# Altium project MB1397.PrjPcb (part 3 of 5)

## Sheet STM32_microcontroller_power.SchDoc: STM32_microcontroller_power
size A4; Date: Not used; ApprovedBy: Not used; CheckedBy: Not used; Author: Not used; CompanyName: STMicroelectronics; DrawnBy: Not used; Engineer: Not used; Organization: Not used; Address1: Not used; Address2: Not used; Address3: Not used; Address4: Not used; DocumentNumber: Not used; Revision: Not used; SheetNumber: 4; SheetTotal: 22
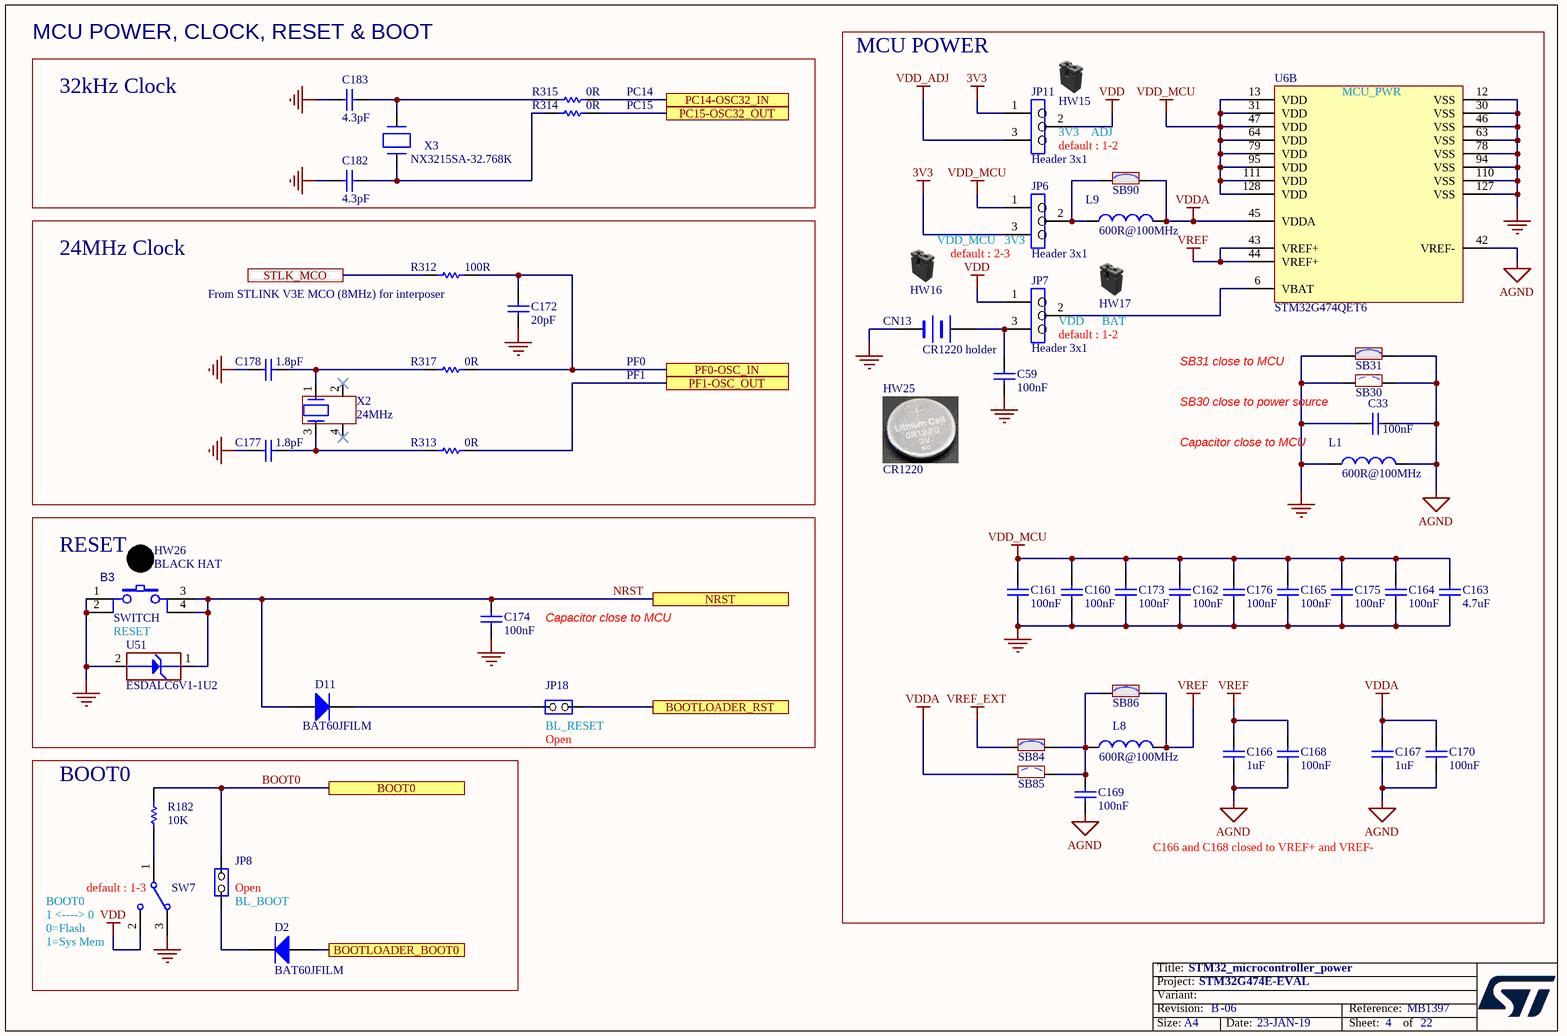
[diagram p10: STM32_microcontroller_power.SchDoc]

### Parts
B3  value SWITCH  [SWI_WEALTHMETAL_TD-0341_4P_BLACK]  (hidden comment: SW-PUSH-CMS)
C33  value 100nF  [C0402]  (hidden comment: Capacitor)
C59  value 100nF  [C0402]  (hidden comment: Capacitor)
C160  value 100nF  [C0402]  (hidden comment: Capacitor)
C161  value 100nF  [C0402]  (hidden comment: Capacitor)
C162  value 100nF  [C0402]  (hidden comment: Capacitor)
C163  value 4.7uF  [C0603]  (hidden comment: Capacitor)
C164  value 100nF  [C0402]  (hidden comment: Capacitor)
C165  value 100nF  [C0402]  (hidden comment: Capacitor)
C166  value 1uF  [C0603]  (hidden comment: Capacitor)
C167  value 1uF  [C0603]  (hidden comment: Capacitor)
C168  value 100nF  [C0402]  (hidden comment: Capacitor)
C169  value 100nF  [C0402]  (hidden comment: Capacitor)
C170  value 100nF  [C0402]  (hidden comment: Capacitor)
C172  value 20pF  [C0402]  (hidden comment: Capacitor)
C173  value 100nF  [C0402]  (hidden comment: Capacitor)
C174  value 100nF  [C0402]  (hidden comment: Capacitor)
C175  value 100nF  [C0402]  (hidden comment: Capacitor)
C176  value 100nF  [C0402]  (hidden comment: Capacitor)
C177  value 1.8pF  [C0402]  (hidden comment: Capacitor)
C178  value 1.8pF  [C0402]  (hidden comment: Capacitor)
C182  value 4.3pF  [C0402]  (hidden comment: Capacitor)
C183  value 4.3pF  [C0402]  (hidden comment: Capacitor)
CN13  value CR1220 holder  [BAT_HARWIN_S8411-45R_SMD_2P]  (hidden comment: BATTERY HOLDER)
D2  BAT60JFILM  [DIO_SOD323]
D11  BAT60JFILM  [DIO_SOD323]
HW15  Shunt Black 2.54mm  (value not drawn)  (mechanical)
HW16  Shunt Black 2.54mm  (value not drawn)  (mechanical)
HW17  Shunt Black 2.54mm  (value not drawn)  (mechanical)
HW25  value CR1220  (hidden comment: BBU_CR1220)  (mechanical)
HW26  value BLACK HAT  (hidden comment: BUTTON_HAT_BLACK)  (mechanical)
JP6  value Header 3x1  [CON_SAMTEC_TSW-103-07-F-S]  (hidden comment: Jumper_Header 3x1)
JP7  value Header 3x1  [CON_SAMTEC_TSW-103-07-F-S]  (hidden comment: Jumper_Header 3x1)
JP8  Jumper_Header 2x1  [CON_SAMTEC_TSW-102-07-G-S]  (value not drawn)
JP11  value Header 3x1  [CON_SAMTEC_TSW-103-07-F-S]  (hidden comment: Jumper_Header 3x1)
JP18  Jumper_Header 2x1  [CON_SAMTEC_TSW-102-07-G-S]  (value not drawn)
L1  value 600R@100MHz  [L0603]  (hidden comment: BEAD)
L8  value 600R@100MHz  [L0603]  (hidden comment: BEAD)
L9  value 600R@100MHz  [L0603]  (hidden comment: BEAD)
R182  value 10K  [R0402]  (hidden comment: Resistor)
R312  value 100R  [R0402]  (hidden comment: Resistor)
R313  value 0R  [R0402]  (hidden comment: Resistor)
R314  value 0R  [R0402]  (hidden comment: Resistor)
R315  value 0R  [R0402]  (hidden comment: Resistor)
R317  value 0R  [R0402]  (hidden comment: Resistor)
SB30  SB_OFF  [SOLDER-BRIDGE_R0603-0R]  (value not drawn)
SB31  SB_ON  [SOLDER-BRIDGE_R0603-0R]  (value not drawn)
SB84  SB_ON  [SOLDER-BRIDGE_R0603-0R]  (value not drawn)
SB85  SB_OFF  [SOLDER-BRIDGE_R0603-0R]  (value not drawn)
SB86  SB_ON  [SOLDER-BRIDGE_R0603-0R]  (value not drawn)
SB90  SB_ON  [SOLDER-BRIDGE_R0603-0R]  (value not drawn)
SW7  SW_MECA_1K2  [SWI_EAO_09-03290-01_EXTENDED_STRAIGHT_BLACK]  (value not drawn)
U6  STM32G474QET6  [ICC_LQFP128_14X14_P040]  (part B of 2)
U51  value ESDALC6V1-1U2  [ESD_ST0201]  (hidden comment: ESD-TRANSIL)
X2  value 24MHz  [CRY_NX2016SA_4P]  (hidden comment: XTAL_4_PINS)
X3  value NX3215SA-32.768K  [CRY_NX3215SA_2P]  (hidden comment: XTAL_2_PINS)

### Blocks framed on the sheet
MCU POWER: C33 C59 C160-C170 C173 C175 C176 CN13 HW15-HW17 HW25 JP6 JP7 JP11 L1 L8 L9 SB30 SB31 SB84-SB86 SB90 U6
24MHz Clock: C172 C177 C178 R312 R313 R317 X2
RESET: B3 C174 D11 HW26 JP18 U51
BOOT0: D2 JP8 R182 SW7

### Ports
BOOT0, BOOTLOADER_BOOT0, BOOTLOADER_RST, NRST, PC14-OSC32_IN, PC15-OSC32_OUT, PF0-OSC_IN, PF1-OSC_OUT, STLK_MCO

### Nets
3V3: JP6.3 JP11.1
AGND: C33.1 C166.1 C167.2 C168.1 C169.1 C170.1 L1.2 SB30.2 SB31.2 U6.42(VREF-)
GND: B3.1 B3.2 C33.2 C59.1 C160.1 C161.1 C162.1 C163.2 C164.1 C165.1 C172.2 C173.1 C174.1 C175.1 C176.1 C177.1 C178.1 C182.1 C183.1 CN13.2(-) L1.1 SB30.1 SB31.1 SW7.3 U6.12(VSS) U6.30(VSS) U6.46(VSS) U6.63(VSS) U6.78(VSS) U6.94(VSS) U6.110(VSS) U6.127(VSS) U51.2(GND)
VDD: JP7.1 JP11.2 SW7.2
VDD_ADJ: JP11.3
VDD_MCU: C160.2 C161.2 C162.2 C163.1 C164.2 C165.2 C173.2 C175.2 C176.2 JP6.1 U6.13(VDD) U6.31(VDD) U6.47(VDD) U6.64(VDD) U6.79(VDD) U6.95(VDD) U6.111(VDD) U6.128(VDD)
VDDA: C167.1 C170.2 L9.2 SB85.1 SB90.2 U6.45(VDDA)
VREF: C166.2 C168.2 L8.2 SB86.2 U6.43(VREF+) U6.44(VREF+)
VREF_EXT: SB84.1
BOOT0: JP8.2(NO) R182.1 ; port BOOT0
NRST: B3.3 B3.4 C174.2 D11.1(A) U51.1(IO1) ; port NRST
PC14: R315.2 ; port PC14-OSC32_IN
PC15: R314.2 ; port PC15-OSC32_OUT
PF0: C172.1 R312.2 R317.2 ; port PF0-OSC_IN
PF1: R313.2 ; port PF1-OSC_OUT
NetC59_2: C59.2 CN13.1(+) JP7.3
NetC169_2: C169.2 L8.1 SB84.2 SB85.2 SB86.1
NetC177_2: C177.2 R313.1 X2.3
NetC178_2: C178.2 R317.1 X2.1
NetC182_2: C182.2 R314.1 X3.1(X1)
NetC183_2: C183.2 R315.1 X3.2(X2)
NetD2_1: D2.1(A) ; port BOOTLOADER_BOOT0
NetD2_2: D2.2(K) JP8.1(COMMON)
NetD11_2: D11.2(K) JP18.1(COMMON)
NetJP6_2: JP6.2 L9.1 SB90.1
NetJP7_2: JP7.2 U6.6(VBAT)
NetJP18_2: JP18.2(NO) ; port BOOTLOADER_RST
NetR182_2: R182.2 SW7.1
NetR312_1: R312.1 ; port STLK_MCO

Not connected (* = marked no-connect by the designer): X2 2* 4*

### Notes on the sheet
- MCU POWER, CLOCK, RESET & BOOT
- 32kHz Clock
- PC14
- PC15
- (near JP11) default : 1-2
- (near JP11) 3V3    ADJ
- VDD_MCU   3V3
- (near R312) From STLINK V3E MCO (8MHz) for interposer
- (near JP6) default : 2-3
- PF0
- PF1
- (near JP7) default : 1-2
- (near JP7) VDD      BAT
- SB31 close to MCU
- (near L1) Capacitor close to MCU
- SB30 close to power source
- (near B3) RESET
- Capacitor close to MCU
- (near JP18) Open
- (near JP18) BL_RESET
- C166 and C168 closed to VREF+ and VREF-
- BOOT0
- (near SW7) 1 <----> 0
- (near SW7) default : 1-3
- (near JP8) Open
- (near JP8) BL_BOOT
- (near SW7) 0=Flash
- (near SW7) 1=Sys Mem

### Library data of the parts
B3 = MCD-00001: Non-Open Push-Button 0.1A 24V BLACK; Manufacturer_Part_Number: TD-0341; Manufacturer: WEALTHMETAL; Part_Type: Misc; Provided_By: SUBCO; Initial_Board_Reference: MB1274; Remark: update MPN removed color, as it is done by HAT, removed Farnell code as it is not good; Path: ws/MCD_ApplicationBoards/Lists/MCDPARTSdatabase; Item Type: Item
C33 C59 C160-C162 C164 C165 C168-C170 C173-C176 = MCD-00006: Capacitor, MLCC, 100nF, 16V, X7R, 10%, 0402, T=0.5mm; Manufacturer_Part_Number: CC0402KRX7R7BB104; Manufacturer: YAGEO; Alternate_Manufacturer_Part_Number: GCM155R71C104KA55D; Alternate_Manufacturer: MURATA; Provided_By: SUBCO; Initial_Board_Reference: MB1274; Path: ws/MCD_ApplicationBoards/Lists/MCDPARTSdatabase; Item Type: Item
C163 = MCD-00009: Capacitor, MLCC, 4.7uF, 16V, X5R, 10%, 0603, T=0.8mm; Manufacturer_Part_Number: CC0603KRX5R7BB475; Manufacturer: YAGEO; Provided_By: SUBCO; Initial_Board_Reference: MB1274; Path: ws/MCD_ApplicationBoards/Lists/MCDPARTSdatabase; Item Type: Item
C166 = MCD-00010: Capacitor, MLCC, 1uF, 16V, X5R, 10%, 0603, T=0,8mm; Manufacturer_Part_Number: CC0603KRX5R7BB105; Manufacturer: YAGEO; Provided_By: SUBCO; ECCN_US: EAR99; ECCN_EU: NEC
C167 = MCD-00010: Capacitor, MLCC, 1uF, 16V, X5R, 10%, 0603, T=0,8mm; Manufacturer_Part_Number: CC0603KRX5R7BB105; Manufacturer: YAGEO; Provided_By: SUBCO; Initial_Board_Reference: MB1274; Path: ws/MCD_ApplicationBoards/Lists/MCDPARTSdatabase; Item Type: Item
C172 = MCD-00016: Capacitor, MLCC, 20pF, 50V, NPO, 5%, 0402, T=0,5mm; Manufacturer_Part_Number: CC0402JRNPO9BN200; Manufacturer: YAGEO; Provided_By: SUBCO; Initial_Board_Reference: MB1274; Path: ws/MCD_ApplicationBoards/Lists/MCDPARTSdatabase; Item Type: Item
C177 C178 = MCD-01598: Capacitor, MLCC, 1.8pF, 50V, NPO, +-0.25pF, 0402, T=0,5mm; Manufacturer_Part_Number: CC0402CRNPO9BN1R8; Manufacturer: YAGEO; Provided_By: SUBCO
C182 C183 = MCD-01706: Capacitor, MLCC, 4.3pF, 50V, NPO, +-0.25pF, 0402, T=0,5mm; Manufacturer_Part_Number: CC0402CRNPO9BN4R3; Manufacturer: YAGEO; Provided_By: SUBCO
CN13 = MCD-00558: Battery Coin Cell holder, CR1220_12mm, Height 4.25mm; Part_Type: Connector; Manufacturer_Part_Number: S8411-45R; Manufacturer: HARWIN; Provided_By: SUBCO; Initial_Board_Reference: MB1331; Path: ws/MCD_ApplicationBoards/Lists/MCDPARTSdatabase; Item Type: Item
D2 D11 = MCD-00034: Manufacturer: STMICROELECTRONICS; Part_Type: Diode; BMS_Part_Number: 9151097; Provided_By: SUBCO with ST control; Initial_Board_Reference: MB1274; Path: ws/MCD_ApplicationBoards/Lists/MCDPARTSdatabase; Item Type: Item
HW15-HW17 = MCD-00043: SHUNT 2.54mm BLACK; Part_Type: Mechanical; Manufacturer_Part_Number: SNT-100-BK-G; Manufacturer: SAMTEC; Provided_By: SUBCO; Initial_Board_Reference: MB1274; Value: SNT-100-BK-G; Path: ws/MCD_ApplicationBoards/Lists/MCDPARTSdatabase; Item Type: Item
HW25 = MCD-01197: Battery Back-Up CR1220,3V,12X2.0MM,35mA; Part_Type: Misc; Manufacturer: tbd; Alternate_Manufacturer_Part_Number: 988.16.04.2.00003; Alternate_Manufacturer: Jiubaba; Provided_By: SUBCO; Initial_Board_Reference: MB1372; Remark: Mechanical part, no footprint.; Path: ws/MCD_ApplicationBoards/Lists/MCDPARTSdatabase; Item Type: Item
HW26 = MCD-00635: Black Hat for switch TD0341X-G01-BLA; Part_Type: Mechanical; Manufacturer_Part_Number: 988.16.09.3.00003_SH-517; Manufacturer: JIUBABA; Provided_By: SUBCO; Initial_Board_Reference: MB1319; Item Type: Item; Path: ws/MCD_ApplicationBoards/Lists/MCDPARTSdatabase
JP6 JP7 JP11 = MCD-00111: Header, 3x1, 2,54mm, VR, TH, Height 5.84mm/2.54mm; Part_Type: Connector; Manufacturer_Part_Number: TSW-103-07-F-S; Manufacturer: SAMTEC; Provided_By: SUBCO; Initial_Board_Reference: MB1262; Path: ws/MCD_ApplicationBoards/Lists/MCDPARTSdatabase; Item Type: Item
JP8 JP18 = MCD-00045: Header, 2x1, 2,54mm, VR, TH, Height 5.84mm/2.54mm; Manufacturer_Part_Number: TSW-102-07-x-S; Manufacturer: SAMTEC; Part_Type: Connector; Value: Shunt not fitted; Provided_By: SUBCO; Initial_Board_Reference: MB1274; Path: ws/MCD_ApplicationBoards/Lists/MCDPARTSdatabase; Item Type: Item
L1 L8 L9 = MCD-00047: SMD Chip ferrite bead, 600R@100MHz +/-25%, 350mA, 500mohm DC, 0603, T=0.8mm; Part_Type: Inductor; Manufacturer_Part_Number: FCM1608KF-601T03; Manufacturer: TAI-TECH; Provided_By: SUBCO; Initial_Board_Reference: MB1274; Path: ws/MCD_ApplicationBoards/Lists/MCDPARTSdatabase; Item Type: Item
R182 = MCD-00053: Resistor,10K,0402,1%,1/16W; Manufacturer_Part_Number: RC0402FR-0710KL; Manufacturer: YAGEO; Provided_By: SUBCO; Initial_Board_Reference: MB1274; Path: ws/MCD_ApplicationBoards/Lists/MCDPARTSdatabase; Item Type: Item
R312 = MCD-00067: Resistor, 100R, 0402, +/- 1%, 1/16W; Manufacturer_Part_Number: RC0402FR-07100RL; Manufacturer: YAGEO; Part_Preference: Recommended; Order_Code_RS: 9239111; Component_Country_Of_Origin: China; ShowFields: YES; ID: 2527
R313-R315 R317 = MCD-00052: Resistor,0R,0402,5%,1/16W; Manufacturer_Part_Number: RC0402JR-070RL; Manufacturer: YAGEO; Provided_By: SUBCO; Initial_Board_Reference: MB1274; Path: ws/MCD_ApplicationBoards/Lists/MCDPARTSdatabase; Item Type: Item
SB30 SB85 = MCD-00072: Solder Bridge OFF; Part_Type: Mechanical; Manufacturer_Part_Number: RC0603JR-070RL; Manufacturer: YAGEO; Provided_By: SUBCO; Initial_Board_Reference: MB1274; Path: ws/MCD_ApplicationBoards/Lists/MCDPARTSdatabase; Item Type: Item
SB31 SB84 = MCD-00071: Solder Bridge ON; Part_Type: Mechanical; Manufacturer_Part_Number: RC0603JR-070RL; Manufacturer: YAGEO; Provided_By: SUBCO; Initial_Board_Reference: MB1274; Path: ws/MCD_ApplicationBoards/Lists/MCDPARTSdatabase; Item Type: Item
SB86 SB90 = MCD-00071: Solder Bridge ON; Part_Type: Mechanical; Manufacturer_Part_Number: RC0603JR-070RL; Manufacturer: YAGEO; Provided_By: SUBCO
SW7 = MCD-00566: Mechanical Slide Switches 1K2 BLK ACT GOLD STRT MNT; Part_Type: Misc; Manufacturer_Part_Number: 09.03290.01; Manufacturer: EAO; Value: Mechanical Slide Switch 1K2; Provided_By: SUBCO; Initial_Board_Reference: MB1331; Path: ws/MCD_ApplicationBoards/Lists/MCDPARTSdatabase; Item Type: Item
U6 = MCD-01212: MCU, ARM Cortex-M4 32-bit, 512KB Flash, 128KB RAM, With Crypto; Part_Type: IC; Manufacturer: STMICROELECTRONICS; BMS_Part_Number: 9175327; Part_Preference: Recommended; Manufacturer_HQ_COO: EU; Order_Code_RS: 193-9856; Component_Country_Of_Origin: Taiwan; ShowFields: YES; ID: 3284
U51 = MCD-00170: ESD protection 6V1; Part_Type: Diode; Manufacturer: STMICROELECTRONICS; BMS_Part_Number: 9151132; Provided_By: SUBCO with ST control; Initial_Board_Reference: MB1274; Path: ws/MCD_ApplicationBoards/Lists/MCDPARTSdatabase; Item Type: Item
X2 = MCD-01036: 24MHz crystal oscillator - Cl:6pf -; Part_Type: Crystal_Osc; Manufacturer_Part_Number: NX2016SA 24MHz EXS00A-CS10820; Manufacturer: NDK; BMS_Part_Number: 9157045; Provided_By: ST; Initial_Board_Reference: MB1332; Path: ws/MCD_ApplicationBoards/Lists/MCDPARTSdatabase; Item Type: Item
X3 = MCD-00091: Crystal 32.768kHz, 6pF, -+20PPM, R=50K, SMD; Part_Type: Crystal_Osc; Manufacturer_Part_Number: NX3215SA 32.768KHz EXS00A-MU00525; Manufacturer: NDK; BMS_Part_Number: 9157034; Provided_By: ST; Initial_Board_Reference: MB1274; Path: ws/MCD_ApplicationBoards/Lists/MCDPARTSdatabase; Item Type: Item

## Sheet Power_Board.SchDoc: Board Power
size A4; Date: Not used; ApprovedBy: Not used; CheckedBy: Not used; Author: Not used; CompanyName: STMicroelectronics; DrawnBy: Not used; Engineer: Not used; Organization: Not used; Address1: Not used; Address2: Not used; Address3: Not used; Address4: Not used; DocumentNumber: Not used; Revision: Not used; SheetNumber: 20; SheetTotal: 22
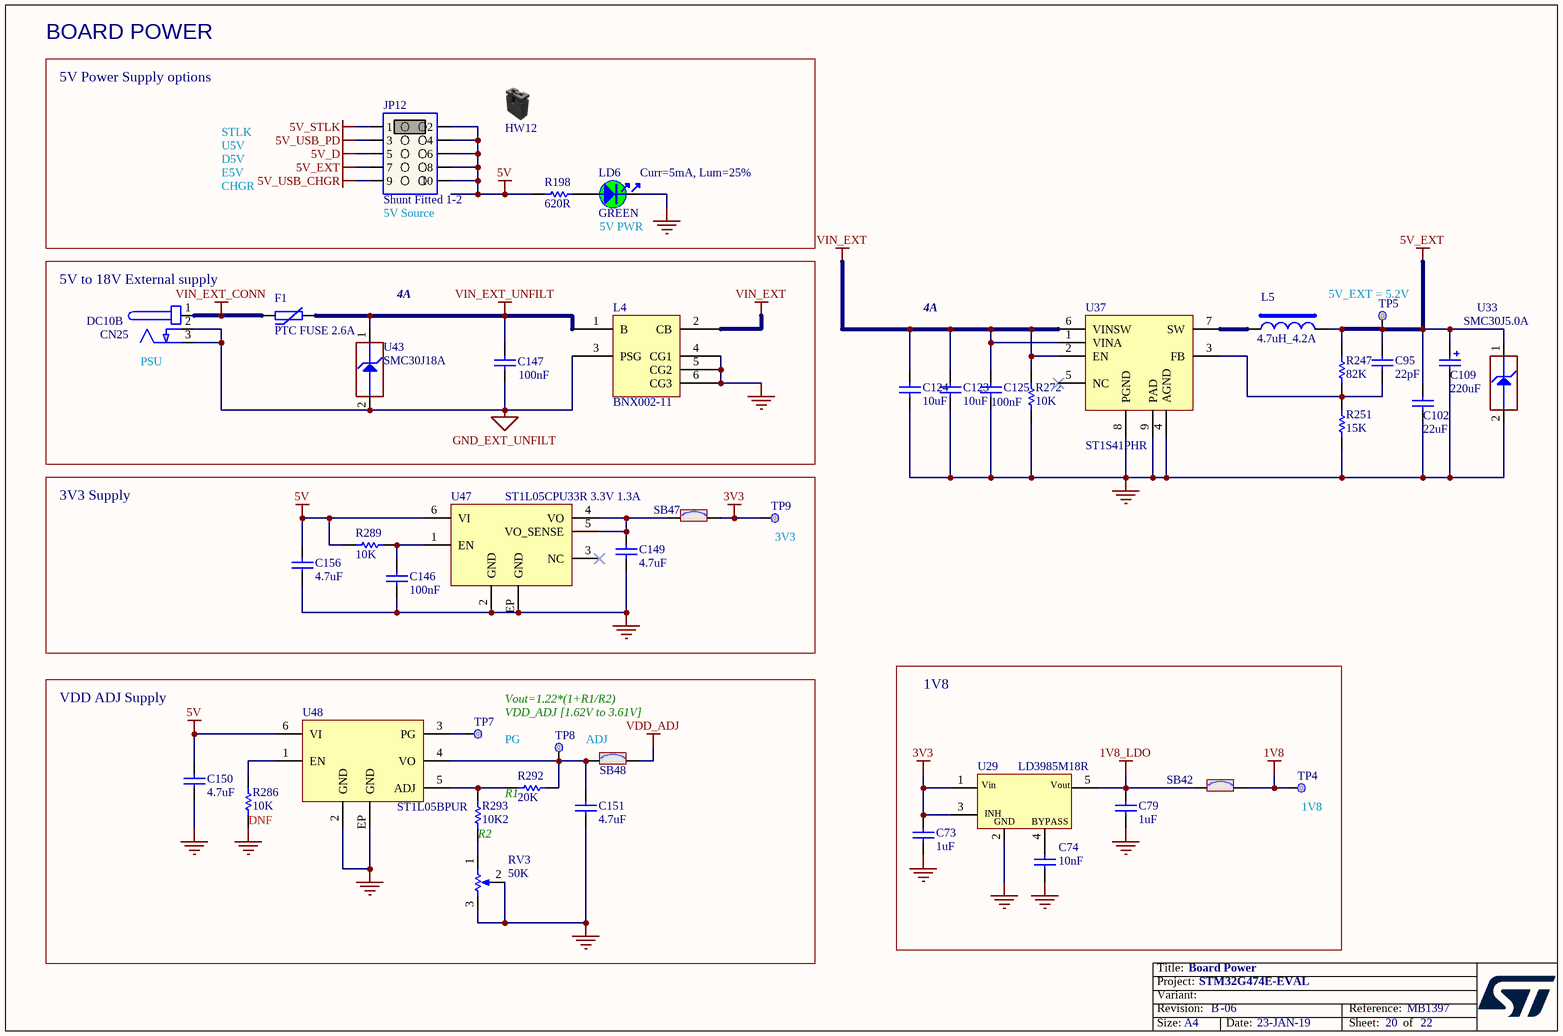
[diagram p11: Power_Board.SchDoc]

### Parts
C73  value 1uF  [C0603]  (hidden comment: Capacitor)
C74  value 10nF  [C0402]  (hidden comment: Capacitor)
C79  value 1uF  [C0603]  (hidden comment: Capacitor)
C95  value 22pF  [C0402]  (hidden comment: Capacitor)
C102  value 22uF  [C0805]  (hidden comment: Capacitor)
C109  value 220uF  [CPOL_TAJ-C_2312_H2P6]  (hidden comment: Cap_POL_TANA)
C123  value 10uF  [C1210]  (hidden comment: Capacitor)
C124  value 10uF  [C1210]  (hidden comment: Capacitor)
C125  value 100nF  [C0402]  (hidden comment: Capacitor)
C146  value 100nF  [C0402]  (hidden comment: Capacitor)
C147  value 100nF  [C0402]  (hidden comment: Capacitor)
C149  value 4.7uF  [C0603]  (hidden comment: Capacitor)
C150  value 4.7uF  [C0603]  (hidden comment: Capacitor)
C151  value 4.7uF  [C0603]  (hidden comment: Capacitor)
C156  value 4.7uF  [C0603]  (hidden comment: Capacitor)
CN25  value DC10B  [CON_DC-POWER-SOCKET_CLIFF_FC68149_DC10B]  (hidden comment: Power_Jack_DC10B)
F1  value PTC FUSE 2.6A  [PTC_BEL-FUSE_1812_0ZCG0260FF2C]  (hidden comment: 0ZCG0260FF2C)
HW12  Shunt Black 2.54mm  (value not drawn)  (mechanical)
JP12  value Shunt Fitted 1-2  [CON_SAMTEC_TSW-105-07-X-D]  (hidden comment: Jumper_Header 5x2 Fitted 1-2)
L4  value BNX002-11  [FIL_MURATA_BNX002-01]  (hidden comment: BNX002-01)
L5  value 4.7uH_4.2A  [IND_TDK_VLS6045EX-4R7M]  (hidden comment: INDUCTOR_POWER)
LD6  value GREEN  [LED_0603_OSRAM_LG-Q396-PS-35_GREEN_1A2K_H0P4]  (hidden comment: LED_green)
R198  value 620R  [R0603]  (hidden comment: Resistor)
R247  value 82K  [R0402]  (hidden comment: Resistor)
R251  value 15K  [R0402]  (hidden comment: Resistor)
R272  value 10K  [R0402]  (hidden comment: Resistor)
R286  value 10K  [R0402]  (hidden comment: Resistor)
R289  value 10K  [R0402]  (hidden comment: Resistor)
R292  value 20K  [R0603]  (hidden comment: Resistor)
R293  value 10K2  [R0603]  (hidden comment: Resistor)
RV3  value 50K  [POT_BOURNS_3386P]  (hidden comment: POTENTIOMETER)
SB42  SB_ON  [SOLDER-BRIDGE_R0603-0R]  (value not drawn)
SB47  SB_ON  [SOLDER-BRIDGE_R0603-0R]  (value not drawn)
SB48  SB_ON  [SOLDER-BRIDGE_R0603-0R]  (value not drawn)
TP4  Test Point  [TP_SMD_1MM]  (value not drawn)  (no BOM)
TP5  Test Point  [TP_SMD_1MM]  (value not drawn)  (no BOM)
TP7  Test Point  [TP_SMD_1MM]  (value not drawn)  (no BOM)
TP8  Test Point  [TP_SMD_1MM]  (value not drawn)  (no BOM)
TP9  Test Point  [TP_SMD_1MM]  (value not drawn)  (no BOM)
U29  LD3985M18R  [REG_SOT23-5L]
U33  value SMC30J5.0A  [DIO_SMC_DO214-AB_1K_2A]  (hidden comment: ESD-TRANSIL)
U37  value ST1S41PHR  [ICC_HSOP8-EPAD_3P90X4P90_P127]  (hidden comment: ST1S41)
U43  value SMC30J18A  [DIO_SMC_DO214-AB_1K_2A]  (hidden comment: ESD-TRANSIL)
U47  value ST1L05CPU33R 3.3V 1.3A  [ICC_DFN6-EPAD_3X3_P095]  (hidden comment: ST1L05CPU33R)
U48  ST1L05BPUR  [ICC_DFN6-EPAD_3X3_P095]

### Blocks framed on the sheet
BOARD POWER: HW12 JP12 LD6 R198
5V to 18V External supply: C147 CN25 F1 L4 U43
3V3 Supply: C146 C149 C156 R289 SB47 TP9 U47
1V8: C73 C74 C79 SB42 TP4 U29
VDD ADJ Supply: C150 C151 R286 R292 R293 RV3 SB48 TP7 TP8 U48

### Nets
1V8: SB42.2 TP4.1
1V8_LDO: C79.2 SB42.1 U29.5(Vout)
3V3: C73.2 SB47.2 TP9.1 U29.1(Vin) U29.3(CE)
5V: C150.1 C156.2 JP12.2 JP12.4 JP12.6 JP12.8 JP12.10 R198.1 R289.2 U47.6(VI) U48.6(VI)
5V_D: JP12.5
5V_EXT: C95.2 C102.2 C109.1 JP12.7 L5.2 R247.2 TP5.1 U33.1(IO1)
5V_STLK: JP12.1
5V_USB_CHGR: JP12.9
5V_USB_PD: JP12.3
GND: C73.1 C74.1 C79.1 C102.1 C109.2 C123.1 C124.1 C125.1 C146.2 C149.1 C150.2 C151.1 C156.1 L4.4(CG1) L4.5(CG2) L4.6(CG3) LD6.2 R251.1 R272.1 R286.2 RV3.2(TAP) RV3.3(TOP) U29.2(GND) U33.2(GND) U37.4(AGND) U37.8(PGND) U37.9(PAD) U47.2(GND) U47.EP(GND) U48.2(GND) U48.EP(GND)
GND_EXT_UNFILT: C147.2 CN25.2 CN25.3 L4.3(PSG) U43.2(GND)
VDD_ADJ: SB48.2
VIN_EXT: C123.2 C124.2 C125.2 L4.2(CB) R272.2 U37.1(VINA) U37.2(EN) U37.6(VINSW)
VIN_EXT_CONN: CN25.1 F1.1
VIN_EXT_UNFILT: C147.1 F1.2 L4.1(B) U43.1(IO1)
NetC74_2: C74.2 U29.4(BYPASS)
NetC95_1: C95.1 R247.1 R251.2 U37.3(FB)
NetC146_1: C146.1 R289.1 U47.1(EN)
NetC149_2: C149.2 SB47.1 U47.4(VO) U47.5(VO_SENSE)
NetC151_2: C151.2 R292.2 SB48.1 TP8.1 U48.4(VO)
NetL5_1: L5.1 U37.7(SW)
NetLD6_1: LD6.1 R198.2
NetR286_1: R286.1 U48.1(EN)
NetR292_1: R292.1 R293.2 U48.5(ADJ)
NetR293_1: R293.1 RV3.1(BOT)
NetTP7_1: TP7.1 U48.3(PG)

Not connected (* = marked no-connect by the designer): U37 5(NC)*; U47 3(NC)*

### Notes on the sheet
- 5V Power Supply options
- D5V
- E5V
- U5V
- STLK
- (near LD6) Curr=5mA, Lum=25%
- CHGR
- (near JP12) 5V Source
- 5V PWR
- (near U43) 4A
- 4A
- (near TP5) 5V_EXT = 5.2V
- (near CN25) PSU
- (near TP9) 3V3
- Vout=1.22*(1+R1/R2)
- VDD_ADJ [1.62V to 3.61V]
- PG
- (near SB48) ADJ
- (near R286) DNF
- (near R293) R2
- (near R292) R1
- (near TP4) 1V8

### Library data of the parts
C73 C79 = MCD-00010: as C167 on sheet STM32_microcontroller_power
C74 = MCD-00011: Capacitor, MLCC, 10nF, 16V, X7R, 10%, 0402, T=0.5mm; Manufacturer_Part_Number: CC0402KRX7R7BB103; Manufacturer: YAGEO; Provided_By: SUBCO; Initial_Board_Reference: MB1274; Path: ws/MCD_ApplicationBoards/Lists/MCDPARTSdatabase; Item Type: Item
C95 = MCD-01995: Capacitor, MLCC, 22pF, 50V, C0G, +/-5%, 0402, T=0.5mm; Part_Preference: Recommended; Manufacturer: TDK; Manufacturer_Part_Number: C1005NP01H220J050BA; Component_Country_Of_Origin: Unknown; ShowFields: YES; ID: 4095
C102 = MCD-00101: Capacitor, MLCC, 22uF, 6V3, X5R, 20%, 0805, T=1,25mm; Manufacturer_Part_Number: GRM21BR60J226ME39L; Manufacturer: MURATA; Provided_By: SUBCO; Initial_Board_Reference: MB1262; Path: ws/MCD_ApplicationBoards/Lists/MCDPARTSdatabase; Item Type: Item
C109 = MCD-00142: Capacitor, Tantalum, 220uF, 10V, 10%, TypeC; Manufacturer_Part_Number: TAJC227K010R; Manufacturer: AVX; Provided_By: SUBCO; Initial_Board_Reference: MB1262; Path: ws/MCD_ApplicationBoards/Lists/MCDPARTSdatabase; Item Type: Item
C123 C124 = MCD-02378: Capacitor, MLCC, 10uF, 50V, X7R, +/-10%, 1210, T=2.5mm; Part_Preference: Recommended; Manufacturer: TDK; Manufacturer_Part_Number: C3225X7R1H106K250AC; Component_Country_Of_Origin: Japan; ShowFields: YES; ID: 4484
C125 C146 C147 = MCD-00006: as C33 on sheet STM32_microcontroller_power
C149-C151 C156 = MCD-00009: as C163 on sheet STM32_microcontroller_power
CN25 = MCD-00173: DC-Power-Jack, 2.5mm, 5A, RA, TH; Manufacturer: CLIFF; Part_Type: Connector; BMS_Part_Number: 9087803; Provided_By: SUBCO; Initial_Board_Reference: MB1265; Path: ws/MCD_ApplicationBoards/Lists/MCDPARTSdatabase; Item Type: Item
F1 = MCD-00624: SMD, PTC resettable fuse, IH:2.6A, IT:5A, Vdc_max:8V, Rmax:47mohm, BELFUSE; Part_Type: Misc; Provided_By: SUBCO; Initial_Board_Reference: MB1264; Path: ws/MCD_ApplicationBoards/Lists/MCDPARTSdatabase; Item Type: Item
HW12 = MCD-00043: as HW15-HW17 on sheet STM32_microcontroller_power
JP12 = MCD-01203: Header, 5x2, 2,54mm, VR, TH, Height 5.84mm/2.54mm - Shunt Fitted 1-2; Part_Type: Connector; Manufacturer_Part_Number: TSW-105-07-x-D; Manufacturer: SAMTEC; Provided_By: SUBCO; Initial_Board_Reference: MB1372; Path: ws/MCD_ApplicationBoards/Lists/MCDPARTSdatabase; Item Type: Item
L4 = MCD-02155: Inductor, DC Power EMI line filter, 40dB min (1MHz - 1GHz) insertion loss, 10A; Part_Preference: Recommended; Manufacturer: MURATA; Component_Country_Of_Origin: Unknown; ShowFields: YES; ID: 4255
L5 = MCD-01239: FIXED IND 4.7UH 4.2A 35 MOHM SMD; Manufacturer_Part_Number: VLS6045EX-4R7M; Manufacturer: TDK; Provided_By: SUBCO; Initial_Board_Reference: MB1397; Path: ws/MCD_ApplicationBoards/Lists/MCDPARTSdatabase; Item Type: Item
LD6 = MCD-00588: LED Green, 0603 SMD, Forward Voltage Typ=2V, Max=2.5V; Part_Type: Display; Manufacturer_Part_Number: LG Q396-PS-35; Manufacturer: OSRAM OPTO SEMICONDUCTORS; Alternate_Manufacturer_Part_Number: VLMTG1300-GS08; Alternate_Manufacturer: VISHAY SEMICONDUCTOR OPTO DIVISION; Provided_By: SUBCO; Initial_Board_Reference: MB1331; Path: ws/MCD_ApplicationBoards/Lists/MCDPARTSdatabase; Item Type: Item
R198 = MCD-00500: Resistor,620R,0603,1%,1/10W; Manufacturer_Part_Number: RC0603FR-07620RL; Manufacturer: YAGEO; Provided_By: SUBCO; Initial_Board_Reference: MBxxxx; Path: ws/MCD_ApplicationBoards/Lists/MCDPARTSdatabase; Item Type: Item
R247 = MCD-00531: Resistor,82K,0402,1%,1/16W; Manufacturer_Part_Number: RC0402FR-0782KL; Manufacturer: YAGEO; Provided_By: SUBCO; Initial_Board_Reference: MBxxxx; Path: ws/MCD_ApplicationBoards/Lists/MCDPARTSdatabase; Item Type: Item
R251 = MCD-00285: Resistor,15K,0402,5%,1/16W; Manufacturer_Part_Number: RC0402JR-0715KL; Manufacturer: YAGEO; Provided_By: SUBCO; Initial_Board_Reference: MB1329; Path: ws/MCD_ApplicationBoards/Lists/MCDPARTSdatabase; Item Type: Item
R272 R286 R289 = MCD-00053: as R182 on sheet STM32_microcontroller_power
R292 = MCD-00422: Resistor,20K,0603,1%,1/10W; Manufacturer_Part_Number: RC0603FR-0720KL; Manufacturer: YAGEO; Provided_By: SUBCO; Initial_Board_Reference: MBxxxx; Path: ws/MCD_ApplicationBoards/Lists/MCDPARTSdatabase; Item Type: Item
R293 = MCD-01155: Resistor,10K2,0603,1%,1/10W; Manufacturer_Part_Number: RC0603FR-0710K2L; Manufacturer: YAGEO; Provided_By: SUBCO; Initial_Board_Reference: MB1372; Path: ws/MCD_ApplicationBoards/Lists/MCDPARTSdatabase; Item Type: Item
RV3 = MCD-01156: TRIMMER 50K OHM 0.5W PC PIN; Part_Type: Resistor; Manufacturer_Part_Number: 3386P-1-503; Manufacturer: BOURNS; Provided_By: SUBCO; Initial_Board_Reference: MB1372; Path: ws/MCD_ApplicationBoards/Lists/MCDPARTSdatabase; Item Type: Item
SB42 SB47 SB48 = MCD-00071: as SB31 on sheet STM32_microcontroller_power
TP4 TP5 TP7-TP9 = MCD-00074: Test Point 1mm; Part_Type: Mechanical; Initial_Board_Reference: MB1274; Path: ws/MCD_ApplicationBoards/Lists/MCDPARTSdatabase; Item Type: Item
U29 = MCD-00078: Ultra low drop-low noise BiCMOS voltage, regulators low ESR capacitors compatible; Manufacturer: STMICROELECTRONICS; Part_Type: IC; BMS_Part_Number: 9176159; Provided_By: SUBCO with ST control; Initial_Board_Reference: MB1274; Path: ws/MCD_ApplicationBoards/Lists/MCDPARTSdatabase; Item Type: Item
U33 = MCD-01231: 3000 W Transil; Part_Type: Diode; Manufacturer: STMICROELECTRONICS; Provided_By: SUBCO with ST control; Initial_Board_Reference: MB1397; Path: ws/MCD_ApplicationBoards/Lists/MCDPARTSdatabase; Item Type: Item
U37 = MCD-01237: 4A step-down switching regulator; Part_Type: IC; Manufacturer: STMICROELECTRONICS; Provided_By: SUBCO with ST control; Initial_Board_Reference: MB1397; Path: ws/MCD_ApplicationBoards/Lists/MCDPARTSdatabase; Item Type: Item
U43 = MCD-01238: 3000 W Transil; Part_Type: Diode; Manufacturer: STMICROELECTRONICS; Provided_By: SUBCO with ST control; Initial_Board_Reference: MB1397; Path: ws/MCD_ApplicationBoards/Lists/MCDPARTSdatabase; Item Type: Item
U47 = MCD-01025: LDO, 3.3V, 1.3A, Very low quiescent current BiCMOS voltage regulator; Part_Type: IC; Manufacturer: STMICROELECTRONICS; BMS_Part_Number: 9176246; Provided_By: SUBCO with ST control; Initial_Board_Reference: MB1331; Path: ws/MCD_ApplicationBoards/Lists/MCDPARTSdatabase; Item Type: Item
U48 = MCD-00581: LDO Linear Voltage Regulator IC Positive Adjustable 1 Output Adjustable 1.3A 6-DFN (3x3); Manufacturer: STMICROELECTRONICS; BMS_Part_Number: 9176239; Provided_By: SUBCO with ST control; Initial_Board_Reference: MB1331; Path: ws/MCD_ApplicationBoards/Lists/MCDPARTSdatabase; Item Type: Item

## Sheet HW_Mechanical_Parts.SchDoc: HW_Mechanical_Parts
size A4; Date: Not used; ApprovedBy: Not used; CheckedBy: Not used; Author: Not used; CompanyName: STMicroelectronics; DrawnBy: Not used; Engineer: Not used; Organization: Not used; Address1: Not used; Address2: Not used; Address3: Not used; Address4: Not used; DocumentNumber: Not used; Revision: Not used; SheetNumber: 22; SheetTotal: 22
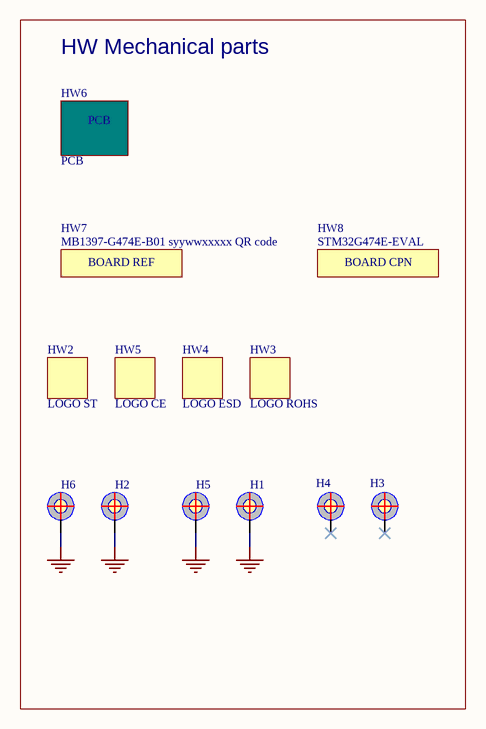
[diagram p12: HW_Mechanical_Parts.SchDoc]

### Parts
H1  POSITION HOLE C7D3R5  [PTH_350_700]  (value not drawn)  (no BOM)
H2  POSITION HOLE C7D3R5  [PTH_350_700]  (value not drawn)  (no BOM)
H3  POSITION HOLE C3R5D3R5  [NPTH_350]  (value not drawn)  (no BOM)
H4  POSITION HOLE C3R5D3R5  [NPTH_350]  (value not drawn)  (no BOM)
H5  POSITION HOLE C7D3R5  [PTH_350_700]  (value not drawn)  (no BOM)
H6  POSITION HOLE C7D3R5  [PTH_350_700]  (value not drawn)  (no BOM)
HW2  value LOGO ST  [LOGO_ST]  (hidden comment: Logo)  (no BOM)
HW3  value LOGO ROHS  [LOGO_ROHS]  (hidden comment: Logo)  (no BOM)
HW4  value LOGO ESD  [LOGO_MAIN_1]  (hidden comment: Logo)  (no BOM)
HW5  value LOGO CE  [LOGO_CE]  (hidden comment: Logo)  (no BOM)
HW6  PCB
HW7  value MB1397-G474E-B01 syywwxxxxx QR code  [STICKER_25X9]  (hidden comment: STICKER_BOARD_REF)  (mechanical)
HW8  value STM32G474E-EVAL  (hidden comment: STICKER_BOARD_CPN)  (mechanical)

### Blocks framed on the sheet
HW Mechanical parts: H1-H6 HW2-HW8

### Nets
GND: H1.1 H2.1 H5.1 H6.1

Not connected (* = marked no-connect by the designer): H3 1*; H4 1*

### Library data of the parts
H1 H2 H5 H6 = MCD-00328: Part_Type: Mechanical; Initial_Board_Reference: MB1311; Path: ws/MCD_ApplicationBoards/Lists/MCDPARTSdatabase; Item Type: Item
H3 H4 = MCD-01368: Part_Type: Mechanical; Initial_Board_Reference: MB1397; Path: ws/MCD_ApplicationBoards/Lists/MCDPARTSdatabase; Item Type: Item
HW2 = MCD-00625: STMicroelectronics logo footprint for PCB; Part_Type: Mechanical; Initial_Board_Reference: MB1331; Path: ws/MCD_ApplicationBoards/Lists/MCDPARTSdatabase; Item Type: Item
HW3 = MCD-00628: ROHS logo footprint for PCB; Part_Type: Mechanical; Initial_Board_Reference: MB1331; Path: ws/MCD_ApplicationBoards/Lists/MCDPARTSdatabase; Item Type: Item
HW4 = MCD-00627: Hand ESD logo footprint for PCB; Part_Type: Mechanical; Initial_Board_Reference: MB1331; Path: ws/MCD_ApplicationBoards/Lists/MCDPARTSdatabase; Item Type: Item
HW5 = MCD-00626: CE logo footprint for PCB; Part_Type: Mechanical; Initial_Board_Reference: MB1331; Path: ws/MCD_ApplicationBoards/Lists/MCDPARTSdatabase; Item Type: Item
HW6 = PCB: Manuf_Part_1: MB1397 PCB; Manuf_1: Jiubaba; Ordered by: Subcon; Fitted: YES
HW7 = MCD-00235: Sticker to mention board reference + serial number; Part_Type: Mechanical; Provided_By: SUBCO; Initial_Board_Reference: MB1319; Path: ws/MCD_ApplicationBoards/Lists/MCDPARTSdatabase; Item Type: Item
HW8 = MCD-00549: Sticker to mention board CPN code; Part_Type: Mechanical; Provided_By: Subcon; Initial_Board_Reference: mb1319

## Sheet Analog_Interfaces.SchDoc: Analog Interfaces
size A4; Date: Not used; ApprovedBy: Not used; CheckedBy: Not used; Author: Not used; CompanyName: STMicroelectronics; DrawnBy: Not used; Engineer: Not used; Organization: Not used; Address1: Not used; Address2: Not used; Address3: Not used; Address4: Not used; DocumentNumber: Not used; Revision: Not used; SheetNumber: 13; SheetTotal: 22
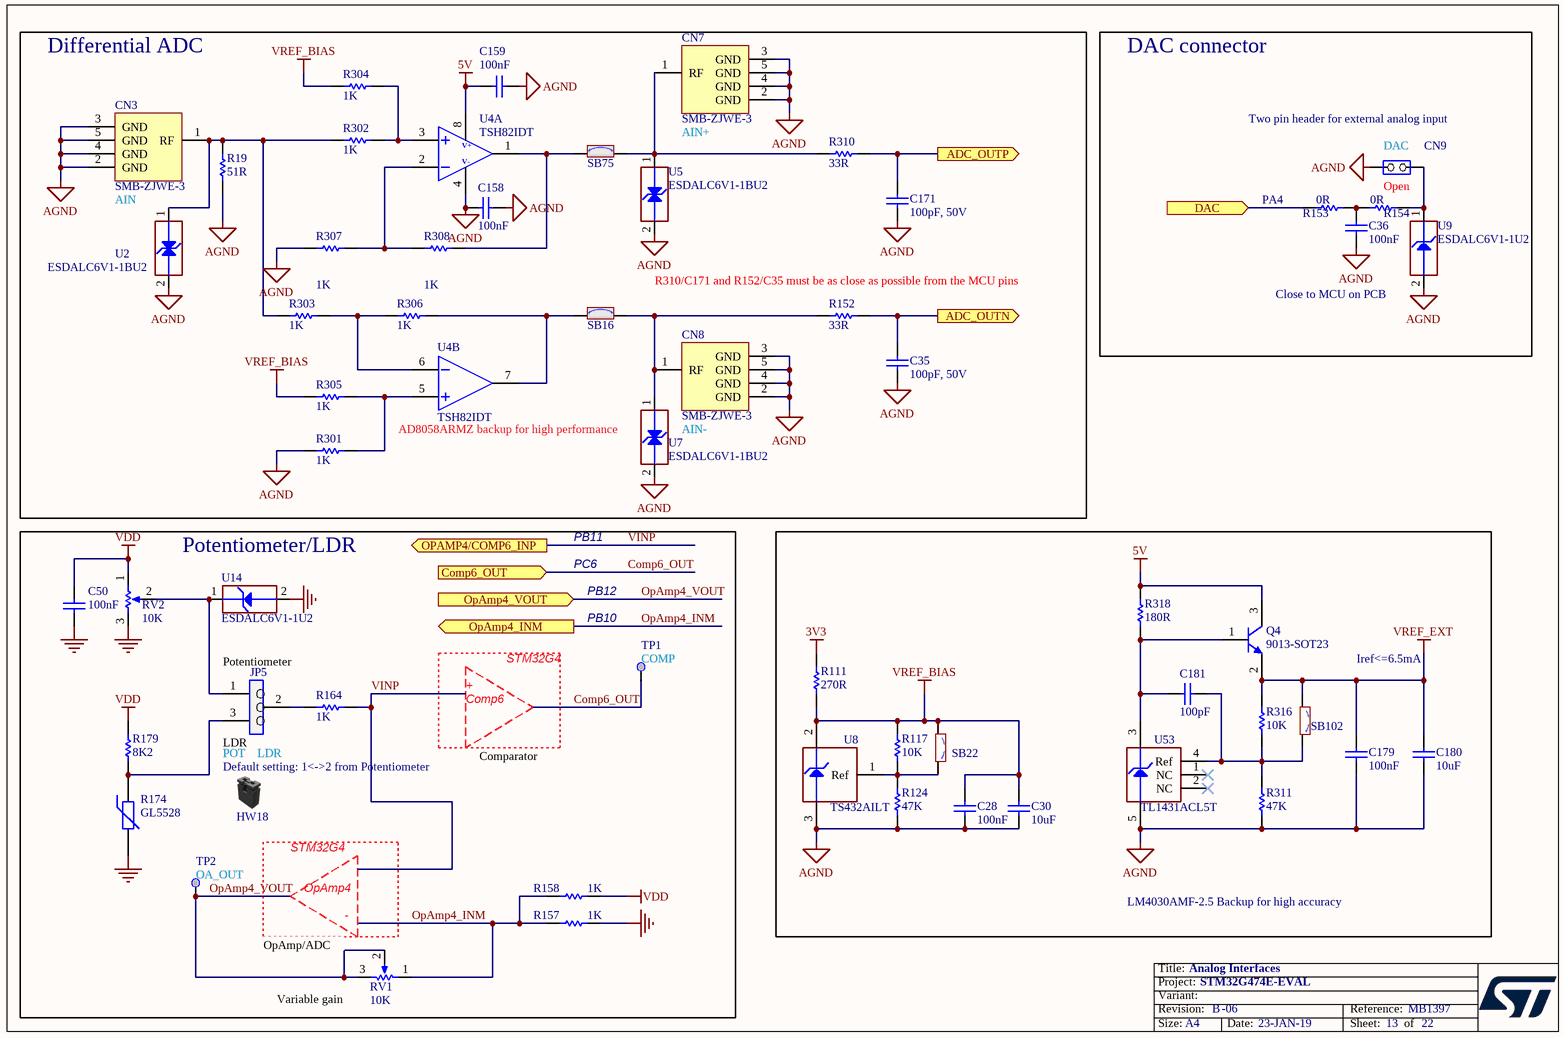
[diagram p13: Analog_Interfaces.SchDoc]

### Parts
C28  value 100nF  [C0603]  (hidden comment: Capacitor)
C30  value 10uF  [C0603]  (hidden comment: Capacitor)
C35  value 100pF, 50V  [C0603]  (hidden comment: Capacitor)
C36  value 100nF  [C0603]  (hidden comment: Capacitor)
C50  value 100nF  [C0402]  (hidden comment: Capacitor)
C158  value 100nF  [C0603]  (hidden comment: Capacitor)
C159  value 100nF  [C0603]  (hidden comment: Capacitor)
C171  value 100pF, 50V  [C0603]  (hidden comment: Capacitor)
C179  value 100nF  [C0603]  (hidden comment: Capacitor)
C180  value 10uF  [C0603]  (hidden comment: Capacitor)
C181  value 100pF  [C0402]  (hidden comment: Capacitor)
CN3  SMB-ZJWE-3  [CON_JACK-RIGHT-ANGLE_YJ-ELECTRONIC_SMB-ZJWE-3]
CN7  SMB-ZJWE-3  [CON_JACK-RIGHT-ANGLE_YJ-ELECTRONIC_SMB-ZJWE-3]
CN8  SMB-ZJWE-3  [CON_JACK-RIGHT-ANGLE_YJ-ELECTRONIC_SMB-ZJWE-3]
CN9  Jumper_Header 2x1  [CON_SAMTEC_TSW-102-07-G-S]  (value not drawn)
HW18  Shunt Black 2.54mm  (value not drawn)  (mechanical)
JP5  Jumper_Header 3x1  [CON_SAMTEC_TSW-103-07-F-S]  (value not drawn)
Q4  9013-SOT23  [NPN_SOT23]
R19  value 51R  [R0603]  (hidden comment: Resistor)
R111  value 270R  [R0603]  (hidden comment: Resistor)
R117  value 10K  [R0603]  (hidden comment: Resistor)
R124  value 47K  [R0603]  (hidden comment: Resistor)
R152  value 33R  [R0603]  (hidden comment: Resistor)
R153  value 0R  [R0603]  (hidden comment: Resistor)
R154  value 0R  [R0603]  (hidden comment: Resistor)
R157  value 1K  [R0603]  (hidden comment: Resistor)
R158  value 1K  [R0603]  (hidden comment: Resistor)
R164  value 1K  [R0603]  (hidden comment: Resistor)
R174  value GL5528  [PHO_SENBAN_GL55XX]  (hidden comment: PT100)
R179  value 8K2  [R0603]  (hidden comment: Resistor)
R301  value 1K  [R0603]  (hidden comment: Resistor)
R302  value 1K  [R0603]  (hidden comment: Resistor)
R303  value 1K  [R0603]  (hidden comment: Resistor)
R304  value 1K  [R0603]  (hidden comment: Resistor)
R305  value 1K  [R0603]  (hidden comment: Resistor)
R306  value 1K  [R0603]  (hidden comment: Resistor)
R307  value 1K  [R0603]  (hidden comment: Resistor)
R308  value 1K  [R0603]  (hidden comment: Resistor)
R310  value 33R  [R0603]  (hidden comment: Resistor)
R311  value 47K  [R0603]  (hidden comment: Resistor)
R316  value 10K  [R0603]  (hidden comment: Resistor)
R318  value 180R  [R0603]  (hidden comment: Resistor)
RV1  value 10K  [POT_BOURNS_3314J-1]  (hidden comment: POTENTIOMETER)
RV2  value 10K  [POT_BOURNS_3386P]  (hidden comment: POTENTIOMETER)
SB16  SB_ON  [SOLDER-BRIDGE_R0603-0R]  (value not drawn)
SB22  SB_OFF  [SOLDER-BRIDGE_R0603-0R]  (value not drawn)
SB75  SB_ON  [SOLDER-BRIDGE_R0603-0R]  (value not drawn)
SB102  SB_OFF  [SOLDER-BRIDGE_R0603-0R]  (value not drawn)
TP1  Test Point  [TP_SMD_1MM]  (value not drawn)  (no BOM)
TP2  Test Point  [TP_SMD_1MM]  (value not drawn)  (no BOM)
U2  value ESDALC6V1-1BU2  [ESD_ST0201]  (hidden comment: ESD-TRANSIL-BIDIR)
U4  TSH82IDT  [ICC_SO8_5X4_P127]  (parts A,B of 2)
U5  value ESDALC6V1-1BU2  [ESD_ST0201]  (hidden comment: ESD-TRANSIL-BIDIR)
U7  value ESDALC6V1-1BU2  [ESD_ST0201]  (hidden comment: ESD-TRANSIL-BIDIR)
U8  TS432AILT  [ICC_SOT23-3L_H1P12]
U9  value ESDALC6V1-1U2  [ESD_ST0201]  (hidden comment: ESD-TRANSIL)
U14  value ESDALC6V1-1U2  [ESD_ST0201]  (hidden comment: ESD-TRANSIL)
U53  TL1431ACL5T  [ICC_SOT23-5L_H1P45]

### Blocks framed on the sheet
Differential ADC: C35 C158 C159 C171 CN3 CN7 CN8 R19 R152 R301-R308 R310 SB16 SB75 U2 U4 U5 U7
DAC connector: C36 CN9 R153 R154 U9
Potentiometer/LDR: C50 HW18 JP5 R157 R158 R164 R174 R179 RV1 RV2 TP1 TP2 U14

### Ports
ADC_OUTN (out), ADC_OUTP (out), Comp6_OUT (in), DAC (in), OPAMP4/COMP6_INP (out), OpAmp4_INM (out), OpAmp4_VOUT (in)

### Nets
3V3: R111.2
5V: C159.2 Q4.3(C) R318.2 U4.8
AGND: C28.1 C30.1 C35.2 C36.2 C158.1 C158.2 C159.1 C171.1 C179.1 C180.1 CN3.2(GND) CN3.3(GND) CN3.4(GND) CN3.5(GND) CN7.2(GND) CN7.3(GND) CN7.4(GND) CN7.5(GND) CN8.2(GND) CN8.3(GND) CN8.4(GND) CN8.5(GND) CN9.2(NO) R19.1 R124.1 R301.2 R307.2 R311.1 U2.2(GND) U4.4 U5.2(GND) U7.2(GND) U8.3(Anode) U9.2(GND) U53.5(Anode)
GND: C50.2 R157.2 R174.2 RV2.3(TOP) U14.2(GND)
VDD: C50.1 R158.2 R179.2 RV2.1(BOT)
VREF_BIAS: C28.2 C30.2 R111.1 R117.2 R304.1 R305.1 SB22.1 U8.2(Cathode)
VREF_EXT: C179.2 C180.2 Q4.2(E) R316.2 SB102.1
ADC_OUTN: C35.1 R152.2 ; port ADC_OUTN
Comp6_OUT: TP1.1 ; port Comp6_OUT
DAC: R153.2 ; port DAC
OpAmp4_INM: R157.1 R158.1 RV1.1(BOT) ; port OpAmp4_INM
OPAMP4_VOUT: RV1.2(TAP) RV1.3(TOP) TP2.1 ; port OpAmp4_VOUT
VINP: R164.1 ; port OPAMP4/COMP6_INP  [project net OPAMP4/COMP6_INP]
NetC36_1: C36.1 R153.1 R154.1
NetC171_2: C171.2 R310.2 ; port ADC_OUTP
NetC181_1: C181.1 R311.2 R316.1 SB102.2 U53.4(Ref)
NetC181_2: C181.2 Q4.1(B) R318.1 U53.3(Cathode)
NetCN3_1: CN3.1(RF) R19.2 R302.1 R303.2 U2.1(IO1)
NetCN7_1: CN7.1(RF) R310.1 SB75.2 U5.1(IO1)
NetCN8_1: CN8.1(RF) R152.1 SB16.2 U7.1(IO1)
NetCN9_1: CN9.1(COMMON) R154.2 U9.1(IO1)
NetJP5_1: JP5.1 RV2.2(TAP) U14.1(IO1)
NetJP5_2: JP5.2 R164.2
NetJP5_3: JP5.3 R174.1 R179.1
NetR117_1: R117.1 R124.2 SB22.2 U8.1(Ref)
NetR301_1: R301.1 R305.2 U4.5
NetR302_2: R302.2 R304.2 U4.3
NetR303_1: R303.1 R306.2 U4.6
NetR306_1: R306.1 SB16.1 U4.7
NetR307_1: R307.1 R308.2 U4.2
NetR308_1: R308.1 SB75.1 U4.1

Not connected (* = marked no-connect by the designer): U53 1(NC)* 2(NC)*

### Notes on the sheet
- AIN+
- (near CN9) Two pin header for external analog input
- (near CN9) DAC
- AIN
- (near R153) PA4
- Open
- (near R152) R310/C171 and R152/C35 must be as close as possible from the MCU pins
- Close to MCU on PCB
- AD8058ARMZ backup for high performance
- AIN-
- PB11
- PC6
- PB12
- (near TP1) PB10
- Potentiometer
- +
- Comp6
- STM32G4
- (near TP1) COMP
- Iref<=6.5mA
- (near JP5) LDR
- (near HW18) Default setting: 1<->2 from Potentiometer
- (near HW18) POT    LDR
- Comparator
- (near TP2) OA_OUT
- OpAmp4
- (near RV1) -
- LM4030AMF-2.5 Backup for high accuracy
- (near RV1) OpAmp/ADC
- (near RV1) Variable gain

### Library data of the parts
C28 C36 C158 C159 C179 = MCD-00211: Capacitor, MLCC, 100nF, 16V, X7R, 10%, 0603, T=0,8mm; Manufacturer_Part_Number: CC0603KRX7R7BB104; Manufacturer: YAGEO; Provided_By: SUBCO; Initial_Board_Reference: MB1319; Path: ws/MCD_ApplicationBoards/Lists/MCDPARTSdatabase; Item Type: Item
C30 C180 = MCD-01124: Capacitor, MLCC, 10µF, 10V, X5R, 10%, 0603, T=0.8mm; Manufacturer_Part_Number: GRM188R61A106KAAL; Manufacturer: MURATA; Provided_By: SUBCO; Initial_Board_Reference: MB1361; Path: ws/MCD_ApplicationBoards/Lists/MCDPARTSdatabase; Item Type: Item
C35 C171 = MCD-01101: Capacitor,100pF,50V,X7R,10%,0603; Manufacturer_Part_Number: 06035C101JAT4A; Manufacturer: AVX; Provided_By: SUBCO; Initial_Board_Reference: MB1381; Path: ws/MCD_ApplicationBoards/Lists/MCDPARTSdatabase; Item Type: Item
C50 = MCD-00006: as C33 on sheet STM32_microcontroller_power
C181 = MCD-00205: Capacitor, MLCC, 100pF, 50V, NPO, 5%, 0402, T=0,5mm; Manufacturer_Part_Number: CC0402JRNPO9BN101; Manufacturer: YAGEO; Provided_By: SUBCO; Initial_Board_Reference: MB1361; Path: ws/MCD_ApplicationBoards/Lists/MCDPARTSdatabase; Item Type: Item
CN3 CN7 CN8 = MCD-01181: SMB type right angle jack for PCB; Part_Type: Connector; Manufacturer: Yangzhou JingCheng Electronic Co., LTD; Provided_By: SUBCO; Initial_Board_Reference: MB1397; Remark: Please validate carefuly the pin number between schematic symbol and footprint as datasheet not mention it.; Path: ws/MCD_ApplicationBoards/Lists/MCDPARTSdatabase; Item Type: Item
CN9 = MCD-00045: as JP8 on sheet STM32_microcontroller_power
HW18 = MCD-00043: as HW15-HW17 on sheet STM32_microcontroller_power
JP5 = MCD-00111: as JP6 on sheet STM32_microcontroller_power
Q4 = MCD-00073: NPN Bipolar Transistor; Part_Type: IC; Manufacturer_Part_Number: BSR14; Manufacturer: NXP; Provided_By: SUBCO; Initial_Board_Reference: MB1274; Path: ws/MCD_ApplicationBoards/Lists/MCDPARTSdatabase; Item Type: Item
R19 = MCD-00486: Resistor,51R,0603,1%,1/10W; Manufacturer_Part_Number: RC0603FR-0751RL; Manufacturer: YAGEO; Provided_By: SUBCO; Initial_Board_Reference: MBxxxx; Path: ws/MCD_ApplicationBoards/Lists/MCDPARTSdatabase; Item Type: Item
R111 = MCD-00442: Resistor,270R,0603,1%,1/10W; Manufacturer_Part_Number: RC0603FR-07270RL; Manufacturer: YAGEO; Provided_By: SUBCO; Initial_Board_Reference: MBxxxx; Path: ws/MCD_ApplicationBoards/Lists/MCDPARTSdatabase; Item Type: Item
R117 R316 = MCD-00220: Resistor,10K,0603,1%,1/10W; Manufacturer_Part_Number: RC0603FR-0710KL; Manufacturer: YAGEO; Provided_By: SUBCO; Initial_Board_Reference: MB1319; Path: ws/MCD_ApplicationBoards/Lists/MCDPARTSdatabase; Item Type: Item
R124 R311 = MCD-00222: Resistor,47K,0603,1%,1/10W; Manufacturer_Part_Number: RC0603FR-0747KL; Manufacturer: YAGEO; Provided_By: SUBCO; Initial_Board_Reference: MB1319; Path: ws/MCD_ApplicationBoards/Lists/MCDPARTSdatabase; Item Type: Item
R152 R310 = MCD-00456: Resistor,33R,0603,1%,1/10W; Manufacturer_Part_Number: RC0603FR-0733RL; Manufacturer: YAGEO; BMS_Part_Number: 9129732; Provided_By: SUBCO; Initial_Board_Reference: MBxxxx; Path: ws/MCD_ApplicationBoards/Lists/MCDPARTSdatabase; Item Type: Item
R153 R154 = MCD-00056: Resistor,0R,0603,5%,1/10W; Manufacturer_Part_Number: RC0603JR-070RL; Manufacturer: YAGEO; Provided_By: SUBCO; Initial_Board_Reference: MB1274; Path: ws/MCD_ApplicationBoards/Lists/MCDPARTSdatabase; Item Type: Item
R157 R158 R164 R301-R308 = MCD-00070: Resistor,1K,0603,1%,1/10W; Manufacturer_Part_Number: RC0603FR-071KL; Manufacturer: YAGEO; Provided_By: SUBCO; Initial_Board_Reference: MB1274; Path: ws/MCD_ApplicationBoards/Lists/MCDPARTSdatabase; Item Type: Item
R174 = MCD-01158: GL55 series  photoconductive cell: Light resistance 10Lux range 10-20KOhm, Dark 1MOhm; Part_Type: Misc; Manufacturer: SHENZHEN SENBAN OPTICAL & ELECTRONIC CO. LTD; Provided_By: SUBCO; Initial_Board_Reference: MB1397; Path: ws/MCD_ApplicationBoards/Lists/MCDPARTSdatabase; Item Type: Item
R179 = MCD-00530: Resistor,8K2,0603,1%,1/10W; Manufacturer_Part_Number: RC0603FR-078K2L; Manufacturer: YAGEO; Provided_By: SUBCO; Initial_Board_Reference: MBxxxx; Path: ws/MCD_ApplicationBoards/Lists/MCDPARTSdatabase; Item Type: Item
R318 = MCD-00342: Resistor,180R,0603,1%,1/10W; Manufacturer_Part_Number: RC0603FR-07180RL; Manufacturer: YAGEO; Provided_By: SUBCO; Initial_Board_Reference: MBxxxx; Path: ws/MCD_ApplicationBoards/Lists/MCDPARTSdatabase; Item Type: Item
RV1 = MCD-01169: 4mm Square Trimming Potentiometer 10K OHM 0.25W PC PIN; Part_Type: Resistor; Manufacturer_Part_Number: 3314J-1-103; Manufacturer: BOURNS; Provided_By: SUBCO; Initial_Board_Reference: MB1397; Path: ws/MCD_ApplicationBoards/Lists/MCDPARTSdatabase; Item Type: Item
RV2 = MCD-00575: TRIMMER 10K OHM 0.5W PC PIN; Part_Type: Resistor; Manufacturer_Part_Number: 3386P-1-103; Manufacturer: BOURNS; Provided_By: SUBCO; Initial_Board_Reference: MB1331; Path: ws/MCD_ApplicationBoards/Lists/MCDPARTSdatabase; Item Type: Item
SB16 SB75 = MCD-00071: as SB31 on sheet STM32_microcontroller_power
SB22 SB102 = MCD-00072: as SB30 on sheet STM32_microcontroller_power
TP1 TP2 = MCD-00074: as TP4 on sheet Power_Board
U2 U5 U7 = MCD-01242: Single-line low capacitance Transil for bidirectional ESD protection 6V1; Part_Type: Diode; Manufacturer: STMICROELECTRONICS; Provided_By: SUBCO with ST control; Initial_Board_Reference: MB1397; Path: ws/MCD_ApplicationBoards/Lists/MCDPARTSdatabase; Item Type: Item
U4 = MCD-01205: Wide-band Rail-to-Rail operational amplifiers with standby function; Part_Type: IC; Manufacturer: STMICROELECTRONICS; Provided_By: SUBCO with ST control; Initial_Board_Reference: MB1397; Path: ws/MCD_ApplicationBoards/Lists/MCDPARTSdatabase; Item Type: Item
U8 = MCD-01204: 1.24V adjustable shunt voltage reference, Precision 0.5%; Part_Type: IC; Manufacturer: STMICROELECTRONICS; Provided_By: SUBCO with ST control; Initial_Board_Reference: MB1397; Remark: PCH: schematics symbol update please to check.Eric: pin 1 and 2 isn't same for schematic and footprint. please find update SchLib on Template.; Path: ws/MCD_ApplicationBoards/Lists/MCDPARTSdatabase; Item Type: Item
U9 U14 = MCD-00170: as U51 on sheet STM32_microcontroller_power
U53 = MCD-01157: Programmable voltage reference; Part_Type: IC; Manufacturer: STMICROELECTRONICS; Provided_By: SUBCO with ST control; Initial_Board_Reference: MB1397; Path: ws/MCD_ApplicationBoards/Lists/MCDPARTSdatabase; Item Type: Item

## Sheet Multi-Function_Expander.SchDoc: Multi-Function Expander
size A3; Date: Not used; ApprovedBy: Not used; CheckedBy: Not used; Author: Not used; CompanyName: STMicroelectronics; DrawnBy: Not used; Engineer: Not used; Organization: Not used; Address1: Not used; Address2: Not used; Address3: Not used; Address4: Not used; DocumentNumber: Not used; Revision: Not used; SheetNumber: 19; SheetTotal: 22
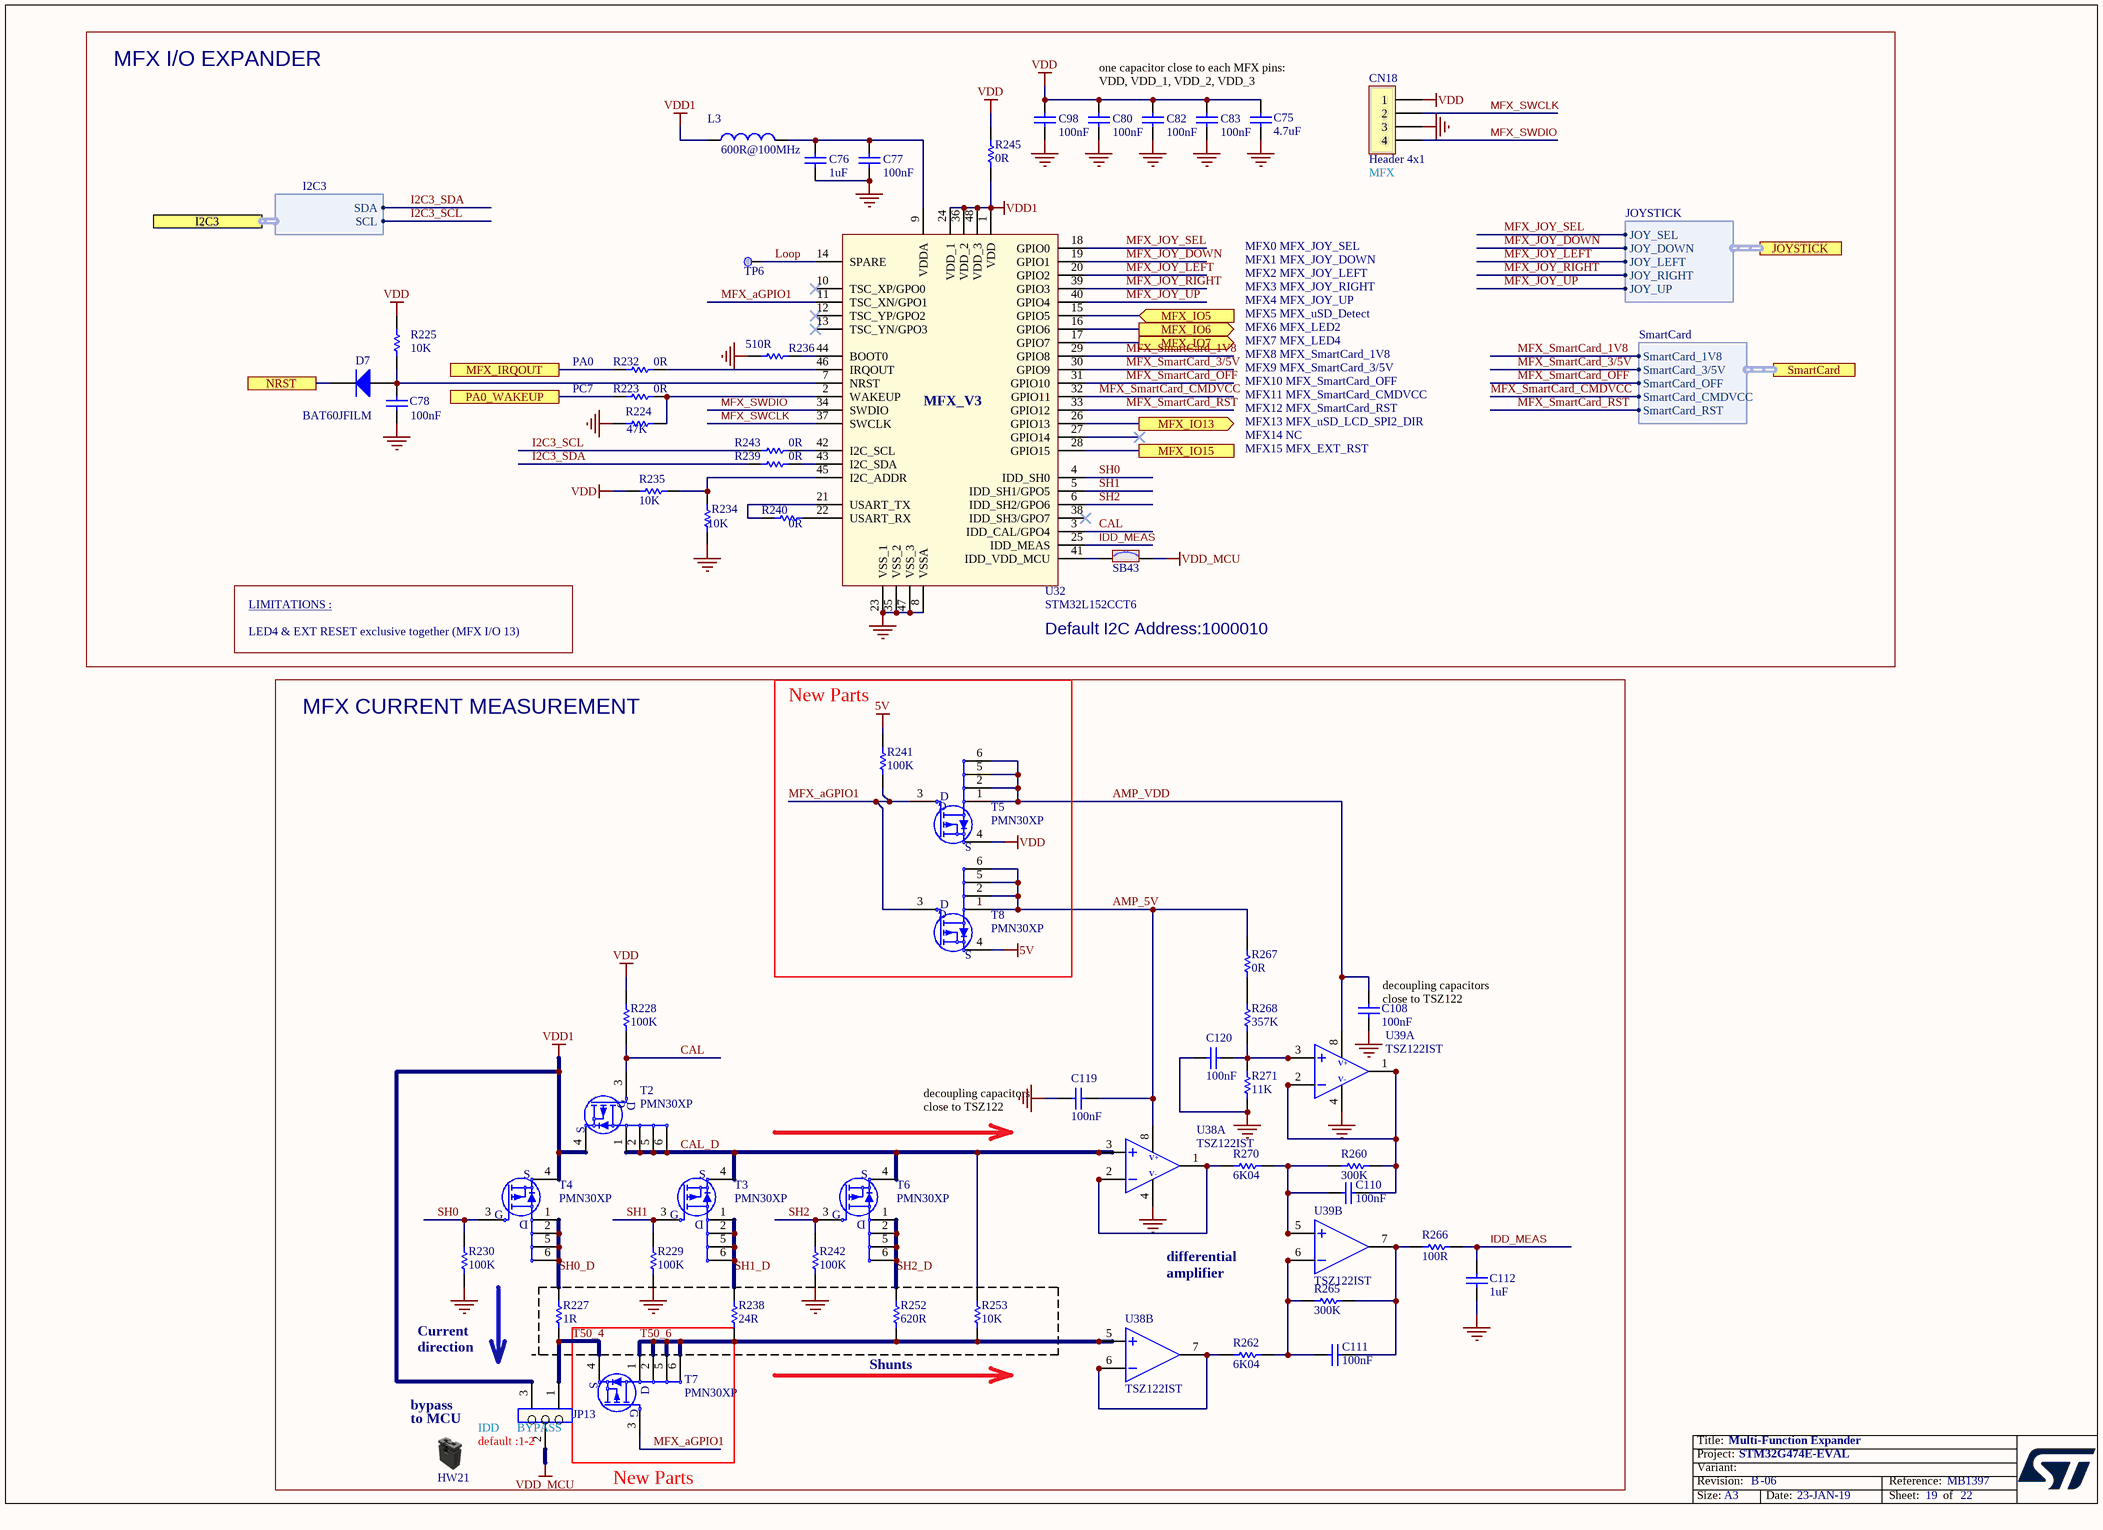
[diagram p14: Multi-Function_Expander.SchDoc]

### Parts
C75  value 4.7uF  [C0603]  (hidden comment: Capacitor)
C76  value 1uF  [C0603]  (hidden comment: Capacitor)
C77  value 100nF  [C0402]  (hidden comment: Capacitor)
C78  value 100nF  [C0402]  (hidden comment: Capacitor)
C80  value 100nF  [C0402]  (hidden comment: Capacitor)
C82  value 100nF  [C0402]  (hidden comment: Capacitor)
C83  value 100nF  [C0402]  (hidden comment: Capacitor)
C98  value 100nF  [C0402]  (hidden comment: Capacitor)
C108  value 100nF  [C0603]  (hidden comment: Capacitor)
C110  value 100nF  [C0603]  (hidden comment: Capacitor)
C111  value 100nF  [C0603]  (hidden comment: Capacitor)
C112  value 1uF  [C0603]  (hidden comment: Capacitor)
C119  value 100nF  [C0603]  (hidden comment: Capacitor)
C120  value 100nF  [C0603]  (hidden comment: Capacitor)
CN18  Header 4x1  [CON_SAMTEC_TSW-104-07-G-S]
D7  BAT60JFILM  [DIO_SOD323]
HW21  Shunt Black 2.54mm  (value not drawn)  (mechanical)
JP13  Jumper_Header 3x1  [CON_SAMTEC_TSW-103-07-F-S]  (value not drawn)
L3  value 600R@100MHz  [L0603]  (hidden comment: BEAD)
R223  value 0R  [R0603]  (hidden comment: Resistor)
R224  value 47K  [R0402]  (hidden comment: Resistor)
R225  value 10K  [R0402]  (hidden comment: Resistor)
R227  value 1R  [R0805]  (hidden comment: Resistor)
R228  value 100K  [R0603]  (hidden comment: Resistor)
R229  value 100K  [R0603]  (hidden comment: Resistor)
R230  value 100K  [R0603]  (hidden comment: Resistor)
R232  value 0R  [R0603]  (hidden comment: Resistor)
R234  value 10K  [R0402]  (hidden comment: Resistor)
R235  value 10K  [R0402]  (hidden comment: Resistor)
R236  value 510R  [R0402]  (hidden comment: Resistor)
R238  value 24R  [R0805]  (hidden comment: Resistor)
R239  value 0R  [R0402]  (hidden comment: Resistor)
R240  value 0R  [R0603]  (hidden comment: Resistor)
R241  value 100K  [R0603]  (hidden comment: Resistor)
R242  value 100K  [R0603]  (hidden comment: Resistor)
R243  value 0R  [R0402]  (hidden comment: Resistor)
R245  value 0R  [R0603]  (hidden comment: Resistor)
R252  value 620R  [R0805]  (hidden comment: Resistor)
R253  value 10K  [R0805]  (hidden comment: Resistor)
R260  value 300K  [R0603]  (hidden comment: Resistor)
R262  value 6K04  [R0603]  (hidden comment: Resistor)
R265  value 300K  [R0603]  (hidden comment: Resistor)
R266  value 100R  [R0402]  (hidden comment: Resistor)
R267  value 0R  [R0603]  (hidden comment: Resistor)
R268  value 357K  [R0603]  (hidden comment: Resistor)
R270  value 6K04  [R0603]  (hidden comment: Resistor)
R271  value 11K  [R0603]  (hidden comment: Resistor)
SB43  SB_ON  [SOLDER-BRIDGE_R0603-0R]  (value not drawn)
T2  PMN30XP  [MOS_SOT23-6L]
T3  PMN30XP  [MOS_SOT23-6L]
T4  PMN30XP  [MOS_SOT23-6L]
T5  PMN30XP  [MOS_SOT23-6L]
T6  PMN30XP  [MOS_SOT23-6L]
T7  PMN30XP  [MOS_SOT23-6L]
T8  PMN30XP  [MOS_SOT23-6L]
TP6  Test Point  [TP_SMD_1MM]  (value not drawn)  (no BOM)
U32  STM32L152CCT6  [ICC_LQFP48_7X7_P050]
U38  TSZ122IST  [ICC_MINISO8_3X3_P065]  (parts A,B of 2)
U39  TSZ122IST  [ICC_MINISO8_3X3_P065]  (parts A,B of 2)

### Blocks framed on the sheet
MFX I/O EXPANDER: C75-C78 C80 C82 C83 C98 CN18 D7 L3 R223-R225 R232 R234-R236 R239 R240 R243 R245 SB43 TP6 U32
MFX CURRENT MEASUREMENT: C108 C110-C112 C119 C120 HW21 JP13 R227-R230 R238 R242 R252 R253 R260 R262 R265-R268 R270 R271 T2-T4 T6 T7 U38 U39
New Parts: R241 T5 T8

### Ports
I2C3 (harness I2C3), JOYSTICK (harness JOYSTICK), MFX_IO5 (in), MFX_IO6 (out), MFX_IO7 (out), MFX_IO13 (out), MFX_IO15, MFX_IRQOUT, NRST, PA0_WAKEUP, SmartCard (harness SmartCard)

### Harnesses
JOYSTICK: JOY_SEL, JOY_LEFT, JOY_DOWN, JOY_RIGHT, JOY_UP
SmartCard: SmartCard_1V8, SmartCard_3/5V, SmartCard_OFF, SmartCard_CMDVCC, SmartCard_RST
I2C3: SDA, SCL

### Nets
5V: R241.2 T8.4(S)
GND: C75.1 C76.1 C77.1 C78.1 C80.1 C82.2 C83.1 C98.1 C108.1 C112.1 C119.1 C120.1 CN18.3 R224.1 R229.1 R230.1 R234.2 R236.2 R242.1 R271.1 U32.8(VSSA) U32.23(VSS_1) U32.35(VSS_2) U32.47(VSS_3) U38.4 U39.4
VDD: C75.2 C80.2 C82.1 C83.2 C98.2 CN18.1 R225.2 R228.2 R235.1 R245.2 T5.4(S)
VDD1: JP13.3 L3.1 R245.1 T2.4(S) T4.4(S) U32.1(VDD) U32.24(VDD_1) U32.36(VDD_2) U32.48(VDD_3)
VDD_MCU: JP13.2 SB43.2
AMP_5V: C119.2 R267.2 T8.1(S) T8.2(S) T8.5(D) T8.6(D) U38.8
AMP_VDD: C108.2 T5.1(S) T5.2(S) T5.5(D) T5.6(D) U39.8
CAL: R228.1 T2.3(G) U32.3(IDD_CAL/GPO4)
CAL_D: R253.2 T2.1(S) T2.2(S) T2.5(D) T2.6(D) T3.4(S) T6.4(S) U38.3
I2C3_SCL: R243.1 ; port I2C3.SCL
I2C3_SDA: R239.1 ; port I2C3.SDA
IDD_MEAS: C112.2 R266.2 U32.25(IDD_MEAS)
Loop: TP6.1 U32.14(SPARE)
MFX_aGPIO1: R241.1 T5.3(G) T7.3(G) T8.3(G) U32.11(TSC_XN/GPO1)
MFX_JOY_DOWN: U32.19(GPIO1) ; port JOYSTICK.JOY_DOWN
MFX_JOY_LEFT: U32.20(GPIO2) ; port JOYSTICK.JOY_LEFT
MFX_JOY_RIGHT: U32.39(GPIO3) ; port JOYSTICK.JOY_RIGHT
MFX_JOY_SEL: U32.18(GPIO0) ; port JOYSTICK.JOY_SEL
MFX_JOY_UP: U32.40(GPIO4) ; port JOYSTICK.JOY_UP
MFX_SmartCard_1V8: U32.29(GPIO8) ; port SmartCard.SmartCard_1V8
MFX_SmartCard_3/5V: U32.30(GPIO9) ; port SmartCard.SmartCard_3/5V
MFX_SmartCard_CMDVCC: U32.32(GPIO11) ; port SmartCard.SmartCard_CMDVCC
MFX_SmartCard_OFF: U32.31(GPIO10) ; port SmartCard.SmartCard_OFF
MFX_SmartCard_RST: U32.33(GPIO12) ; port SmartCard.SmartCard_RST
MFX_SWCLK: CN18.2 U32.37(SWCLK)
MFX_SWDIO: CN18.4 U32.34(SWDIO)
NRST: D7.2(K) ; port NRST
SH0: R230.2 T4.3(G) U32.4(IDD_SH0)
SH0_D: R227.2 T4.1(S) T4.2(S) T4.5(D) T4.6(D)
SH1: R229.2 T3.3(G) U32.5(IDD_SH1/GPO5)
SH1_D: R238.2 T3.1(S) T3.2(S) T3.5(D) T3.6(D)
SH2: R242.2 T6.3(G) U32.6(IDD_SH2/GPO6)
SH2_D: R252.2 T6.1(S) T6.2(S) T6.5(D) T6.6(D)
T50_4: JP13.1 R227.1 T7.4(S)
T50_6: R238.1 R252.1 R253.1 T7.1(S) T7.2(S) T7.5(D) T7.6(D) U38.5
NetC76_2: C76.2 C77.2 L3.2 U32.9(VDDA)
NetC78_2: C78.2 D7.1(A) R225.1 U32.7(NRST)
NetC110_1: C110.1 R260.1 R270.2 U39.5
NetC110_2: C110.2 R260.2 U39.1 U39.2
NetC111_1: C111.1 R262.2 R265.1 U39.6
NetC111_2: C111.2 R265.2 R266.1 U39.7
NetC120_2: C120.2 R268.1 R271.2 U39.3
NetR223_1: R223.1 R224.2 U32.2(WAKEUP)
NetR223_2: R223.2 ; port PA0_WAKEUP
NetR232_1: R232.1 ; port MFX_IRQOUT
NetR232_2: R232.2 U32.46(IRQOUT)
NetR234_1: R234.1 R235.2 U32.45(I2C_ADDR)
NetR236_1: R236.1 U32.44(BOOT0)
NetR239_2: R239.2 U32.43(I2C_SDA)
NetR240_1: R240.1 U32.21(USART_TX)
NetR240_2: R240.2 U32.22(USART_RX)
NetR243_2: R243.2 U32.42(I2C_SCL)
NetR262_1: R262.1 U38.6 U38.7
NetR267_1: R267.1 R268.2
NetR270_1: R270.1 U38.1 U38.2
NetSB43_1: SB43.1 U32.41(IDD_VDD_MCU)
NetU32_15: U32.15(GPIO5) ; port MFX_IO5
NetU32_16: U32.16(GPIO6) ; port MFX_IO6
NetU32_17: U32.17(GPIO7) ; port MFX_IO7
NetU32_26: U32.26(GPIO13) ; port MFX_IO13
NetU32_28: U32.28(GPIO15) ; port MFX_IO15

Not connected (* = marked no-connect by the designer): U32 10(TSC_XP/GPO0)* 12(TSC_YP/GPO2)* 13(TSC_YN/GPO3)* 27(GPIO14)* 38(IDD_SH3/GPO7)*

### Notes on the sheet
- one capacitor close to each MFX pins: VDD, VDD_1, VDD_2, VDD_3
- (near CN18) MFX
- PA0
- PC7
- MFX0	MFX_JOY_SEL
  MFX1	MFX_JOY_DOWN
  MFX2	MFX_JOY_LEFT
  MFX3	MFX_JOY_RIGHT
  MFX4	MFX_JOY_UP
  MFX5	MFX_uSD_Detect
  MFX6	MFX_LED2
  MFX7	MFX_LED4
  MFX8	MFX_SmartCard_1V8
  MFX9	MFX_SmartCard_3/5V
  MFX10	MFX_SmartCard_OFF
  MFX11	MFX_SmartCard_CMDVCC
  MFX12	MFX_SmartCard_RST
  MFX13	MFX_uSD_LCD_SPI2_DIR
  MFX14	NC
  MFX15	MFX_EXT_RST
- LIMITATIONS :
- LED4 & EXT RESET exclusive together (MFX I/O 13)
- (near U32) Default I2C Address:1000010
- (near C108) decoupling capacitors
  close to TSZ122
- (near C119) decoupling capacitors
  close to TSZ122
- differential
  amplifier
- Current direction
- Shunts
- (near HW21) to MCU
- (near HW21) bypass
- (near JP13) IDD      BYPASS
- (near JP13) default :1-2
- New Parts

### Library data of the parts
C75 = MCD-00009: as C163 on sheet STM32_microcontroller_power
C76 C112 = MCD-00010: as C167 on sheet STM32_microcontroller_power
C77 C78 C80 C82 C83 C98 = MCD-00006: as C33 on sheet STM32_microcontroller_power
C108 C110 C111 C119 C120 = MCD-00211: as C28 on sheet Analog_Interfaces
CN18 = MCD-00029: Header, 4x1, 2,54mm, VR, TH, Height 5.84mm/2.54mm; Manufacturer_Part_Number: TSW-104-07-x-S; Manufacturer: SAMTEC; Part_Type: Connector; Provided_By: SUBCO; Initial_Board_Reference: MB1274; Path: ws/MCD_ApplicationBoards/Lists/MCDPARTSdatabase; Item Type: Item
D7 = MCD-00034: as D2 on sheet STM32_microcontroller_power
HW21 = MCD-00043: as HW15-HW17 on sheet STM32_microcontroller_power
JP13 = MCD-00111: as JP6 on sheet STM32_microcontroller_power
L3 = MCD-00047: as L1 on sheet STM32_microcontroller_power
R223 R232 R240 R245 R267 = MCD-00056: as R153 on sheet Analog_Interfaces
R224 = MCD-00063: Resistor,47K,0402,1%,1/16W; Manufacturer_Part_Number: RC0402FR-0747KL; Manufacturer: YAGEO; Provided_By: SUBCO; Initial_Board_Reference: MB1274; Path: ws/MCD_ApplicationBoards/Lists/MCDPARTSdatabase; Item Type: Item
R225 R234 R235 = MCD-00053: as R182 on sheet STM32_microcontroller_power
R227 = MCD-00323: Resistor, 1R, 0805, 1%, 1/8W; Manufacturer_Part_Number: RC0805FR-071RL; Manufacturer: YAGEO; Provided_By: SUBCO; Initial_Board_Reference: MB1311; Path: ws/MCD_ApplicationBoards/Lists/MCDPARTSdatabase; Item Type: Item
R228-R230 R241 R242 = MCD-00223: Resistor,100K,0603,1%,1/10W; Manufacturer_Part_Number: RC0603FR-07100KL; Manufacturer: YAGEO; Provided_By: SUBCO; Initial_Board_Reference: MB1319; Path: ws/MCD_ApplicationBoards/Lists/MCDPARTSdatabase; Item Type: Item
R236 = MCD-00064: Resistor,510R,0402,1%,1/16W; Manufacturer_Part_Number: RC0402FR-07510RL; Manufacturer: YAGEO; Provided_By: SUBCO; Initial_Board_Reference: MB1274; Path: ws/MCD_ApplicationBoards/Lists/MCDPARTSdatabase; Item Type: Item
R238 = MCD-01152: Resistor,24R,0805,1%,1/8W; Manufacturer_Part_Number: RC0805FR-0724RL; Manufacturer: YAGEO; Provided_By: SUBCO; Initial_Board_Reference: MB1372; Path: ws/MCD_ApplicationBoards/Lists/MCDPARTSdatabase; Item Type: Item
R239 R243 = MCD-00052: as R313-R315 on sheet STM32_microcontroller_power
R252 = MCD-01153: Resistor,620R,0805,1%,1/8W; Manufacturer_Part_Number: RC0805FR-07620RL; Manufacturer: YAGEO; Provided_By: SUBCO; Initial_Board_Reference: MB1372; Path: ws/MCD_ApplicationBoards/Lists/MCDPARTSdatabase; Item Type: Item
R253 = MCD-01154: Resistor,10K,0805,1%,1/8W; Manufacturer_Part_Number: RC0805FR-0710KL; Manufacturer: YAGEO; Provided_By: SUBCO; Initial_Board_Reference: MB1372; Path: ws/MCD_ApplicationBoards/Lists/MCDPARTSdatabase; Item Type: Item
R260 R265 = MCD-00454: Resistor,300K,0603,1%,1/10W; Manufacturer_Part_Number: RC0603FR-07300KL; Manufacturer: YAGEO; Provided_By: SUBCO; Initial_Board_Reference: MBxxxx; Path: ws/MCD_ApplicationBoards/Lists/MCDPARTSdatabase; Item Type: Item
R262 R270 = MCD-01151: Resistor,6K04,0603,1%,1/10W; Manufacturer_Part_Number: RC0603FR-076K04L; Manufacturer: YAGEO; Provided_By: SUBCO; Initial_Board_Reference: MB1372; Path: ws/MCD_ApplicationBoards/Lists/MCDPARTSdatabase; Item Type: Item
R266 = MCD-00067: as R312 on sheet STM32_microcontroller_power
R268 = MCD-01150: Resistor,357K,0603,1%,1/10W; Manufacturer_Part_Number: RC0603FR-07357KL; Manufacturer: YAGEO; Provided_By: SUBCO; Initial_Board_Reference: MB1372; Path: ws/MCD_ApplicationBoards/Lists/MCDPARTSdatabase; Item Type: Item
R271 = MCD-00366: Resistor,11K,0603,1%,1/10W; Manufacturer_Part_Number: RC0603FR-0711KL; Manufacturer: YAGEO; Provided_By: SUBCO; Initial_Board_Reference: MBxxxx; Path: ws/MCD_ApplicationBoards/Lists/MCDPARTSdatabase; Item Type: Item
SB43 = MCD-00071: as SB31 on sheet STM32_microcontroller_power
T2-T8 = MCD-01926: 20 V, P-channel Trench MOSFET; Part_Type: IC; Manufacturer: NEXPERIA; Provided_By: SUBCO; Order_Code_RS: 153-0671; ECCN_US: EAR99; ECCN_EU: NEC
TP6 = MCD-00074: as TP4 on sheet Power_Board
U32 = MCD-00135: Ultra-low-power 32-bit MCU ARM; Manufacturer: STMICROELECTRONICS; Part_Type: IC; Provided_By: SUBCO with ST control; Initial_Board_Reference: MB1262; Path: ws/MCD_ApplicationBoards/Lists/MCDPARTSdatabase; Item Type: Item
U38 U39 = MCD-00325: Very high accuracy (5 µV) zero drift micropower 5 V operational amplifiers; Part_Type: IC; Manufacturer: STMICROELECTRONICS; BMS_Part_Number: 9177443; Provided_By: SUBCO with ST control; Initial_Board_Reference: MB1311; Path: ws/MCD_ApplicationBoards/Lists/MCDPARTSdatabase; Item Type: Item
